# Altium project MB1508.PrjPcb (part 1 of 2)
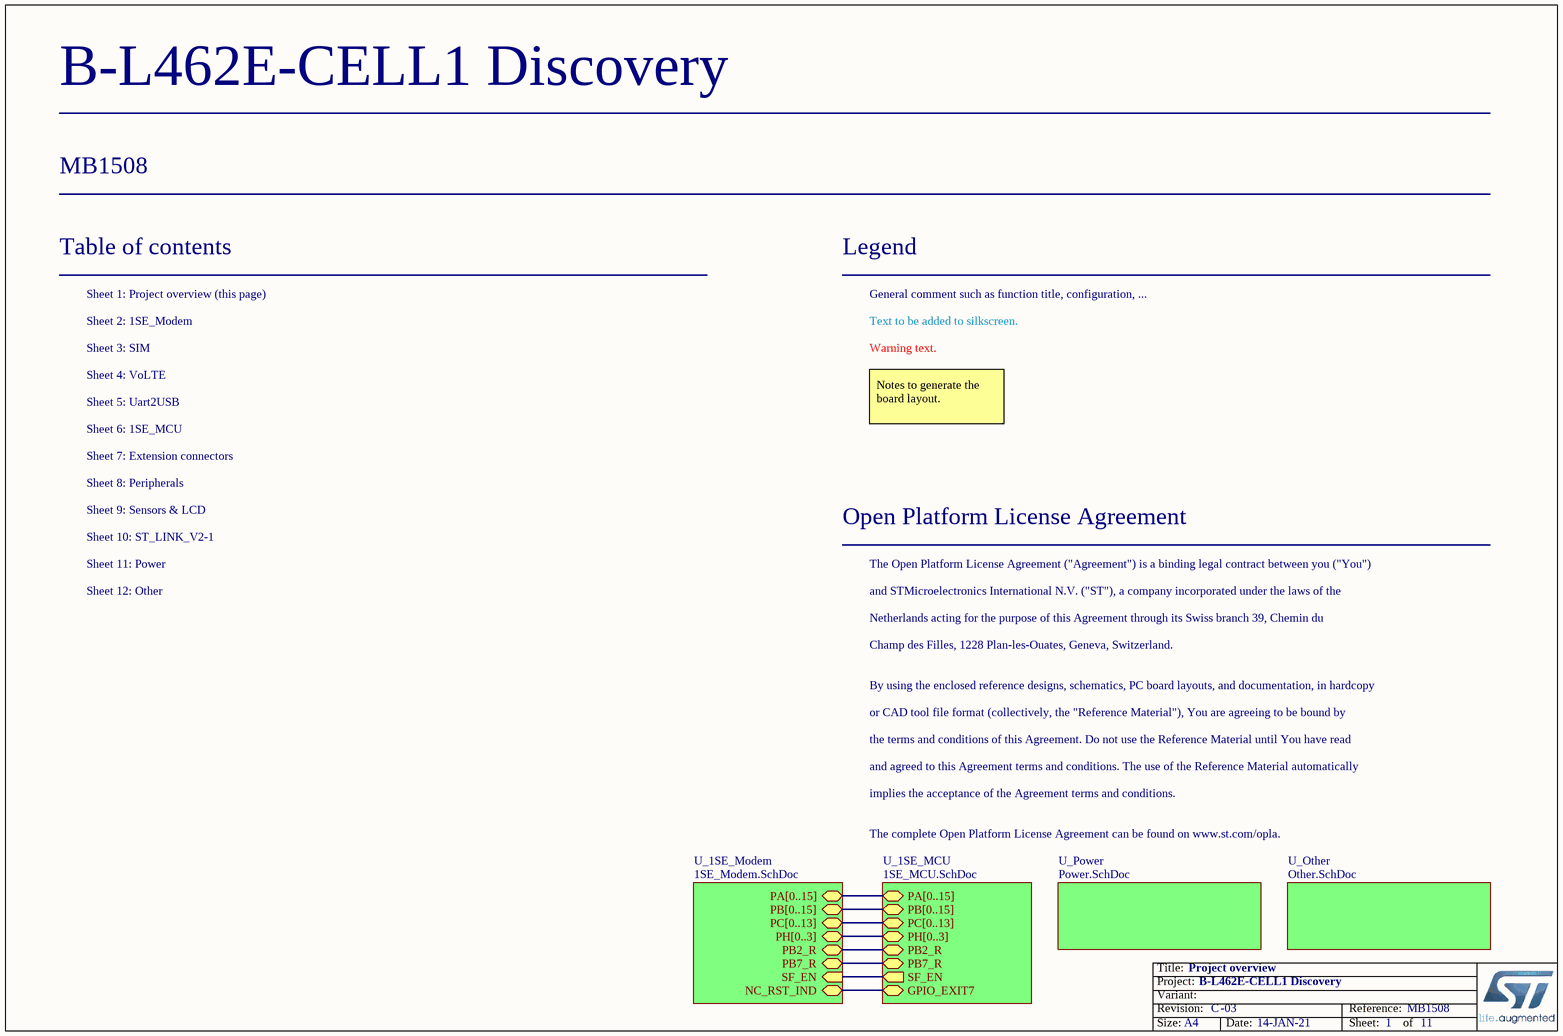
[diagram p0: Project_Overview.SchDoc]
Board_Reference: MB1508; Board_PCB_Revision: C; Board_Name: B-L462E-CELL1 Discovery; Board_Document_Date: 14-JAN-21; Board_Assembly_Revision: 03
12 sheets, 408 parts. Net scope: hierarchical (ports join the sheet entries above them; power ports are global).
Board file: MB1508.PcbDoc
Sheets:
  Project_Overview.SchDoc
    U_Power = Power.SchDoc
    U_1SE_Modem = 1SE_Modem.SchDoc
      U_VoLTE = VoLTE.SchDoc
      U_Uart2USB = Uart2USB.SchDoc
      U_SIM = SIM.SchDoc
    U_1SE_MCU = 1SE_MCU.SchDoc
      U_Extension connectors = Extension connectors.SchDoc
      U_Peripherals = Peripherals.SchDoc
      U_Sensors & LCD = Sensors & LCD.SchDoc
      U_ST_LINK_V2-1 = ST_LINK_V2-1.SchDoc
    U_Other = Other.SchDoc

## Sheet Project_Overview.SchDoc: Project overview
size A4; Date: Not used; ApprovedBy: Not used; CheckedBy: Not used; Author: Not used; CompanyName: STMicroelectronics; DrawnBy: Not used; Engineer: Not used; Organization: Not used; Address1: Not used; Address2: Not used; Address3: Not used; Address4: Not used; DocumentNumber: Not used; Revision: Not used; SheetNumber: 1; SheetTotal: 11

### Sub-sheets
U_1SE_MCU = 1SE_MCU.SchDoc: SF_EN (out), GPIO_EXIT7 (bidir), PA[0..15] (bidir), PB[0..15] (bidir), PC[0..13] (bidir), PH[0..3] (bidir), PB7_R (bidir), PB2_R (bidir)
U_1SE_Modem = 1SE_Modem.SchDoc: PA[0..15] (bidir), PB[0..15] (bidir), PC[0..13] (bidir), PH[0..3] (bidir), NC_RST_IND (bidir), PB7_R (bidir), PB2_R (bidir), SF_EN (in)
U_Other = Other.SchDoc: no entries
U_Power = Power.SchDoc: no entries

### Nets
NC_RST_IND: sheet U_1SE_Modem/NC_RST_IND, sheet U_1SE_MCU/GPIO_EXIT7
PB2_R: sheet U_1SE_Modem/PB2_R, sheet U_1SE_MCU/PB2_R
PB7_R: sheet U_1SE_Modem/PB7_R, sheet U_1SE_MCU/PB7_R
SF_EN: sheet U_1SE_Modem/SF_EN, sheet U_1SE_MCU/SF_EN

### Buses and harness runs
bus sheet U_1SE_MCU/PA[0..15] = sheet U_1SE_Modem/PA[0..15]
bus sheet U_1SE_MCU/PB[0..15] = sheet U_1SE_Modem/PB[0..15]
bus sheet U_1SE_MCU/PC[0..13] = sheet U_1SE_Modem/PC[0..13]
bus sheet U_1SE_MCU/PH[0..3] = sheet U_1SE_Modem/PH[0..3]

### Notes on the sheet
- Table of contents
- Sheet 1: Project overview (this page)
- Legend
- General comment such as function title, configuration, ...
- Sheet 2: 1SE_Modem
- Sheet 3: SIM
- Sheet 4: VoLTE
- Text to be added to silkscreen.
- Warning text.
- Sheet 6: 1SE_MCU
- Sheet 5: Uart2USB
- Notes to generate the board layout.
- Sheet 7: Extension connectors
- Sheet 9: Sensors & LCD
- Sheet 8: Peripherals
- Sheet 11: Power
- Sheet 10: ST_LINK_V2-1
- Open Platform License Agreement
- The Open Platform License Agreement ("Agreement") is a binding legal contract between you ("You")
- Sheet 12: Other
- and STMicroelectronics International N.V. ("ST"), a company incorporated under the laws of the
- Netherlands acting for the purpose of this Agreement through its Swiss branch 39, Chemin du
- Champ des Filles, 1228 Plan-les-Ouates, Geneva, Switzerland.
- By using the enclosed reference designs, schematics, PC board layouts, and documentation, in hardcopy
- or CAD tool file format (collectively, the "Reference Material"), You are agreeing to be bound by
- the terms and conditions of this Agreement. Do not use the Reference Material until You have read
- and agreed to this Agreement terms and conditions. The use of the Reference Material automatically
- implies the acceptance of the Agreement terms and conditions.
- The complete Open Platform License Agreement can be found on www.st.com/opla.

## Sheet Power.SchDoc: Power
size A4; Date: Not used; ApprovedBy: Not used; CheckedBy: Not used; Author: Not used; CompanyName: STMicroelectronics; DrawnBy: Not used; Engineer: Not used; Organization: Not used; Address1: Not used; Address2: Not used; Address3: Not used; Address4: Not used; DocumentNumber: Not used; Revision: Not used; SheetNumber: 11; SheetTotal: 12
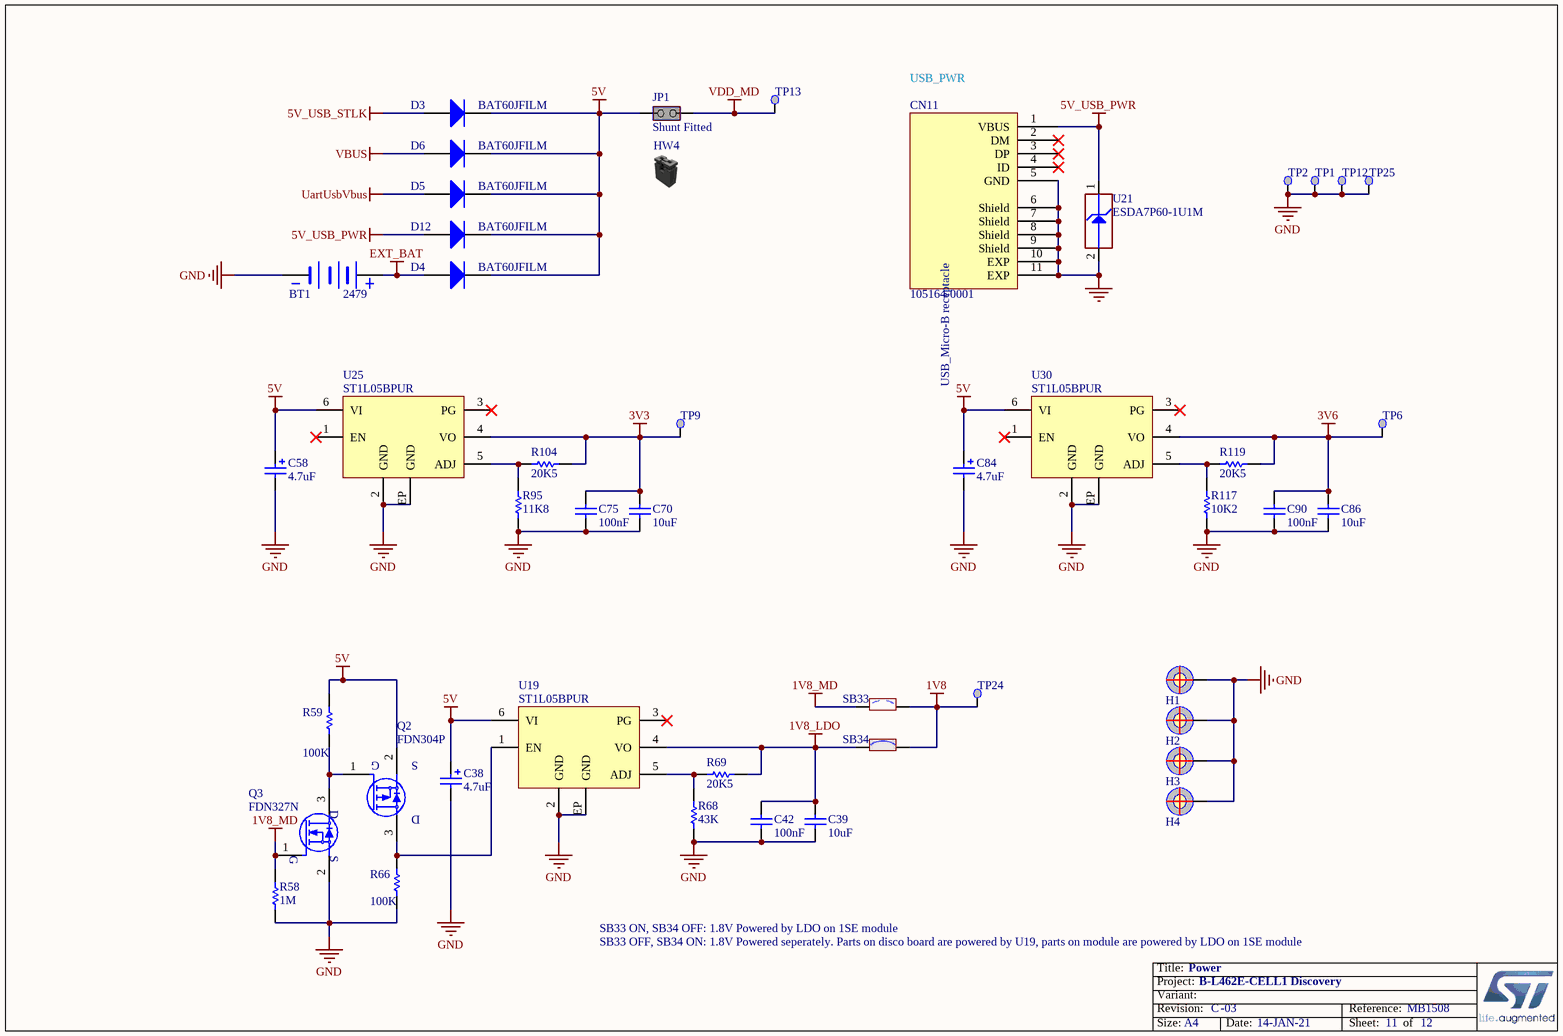
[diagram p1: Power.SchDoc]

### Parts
BT1  value 2479  [BAT_KEYSTONE_PC-MOUNT-2479_HOLDER_AAA_X3]  (hidden comment: BATTERY HOLDER 3 x AAA)
C38  value 4.7uF  [CPOL_TAJ-A_1206_H180]  (hidden comment: Cap_POL_TANA)
C39  value 10uF  [C0805]  (hidden comment: Capacitor)
C42  value 100nF  [C0603]  (hidden comment: Capacitor)
C58  value 4.7uF  [CPOL_TAJ-A_1206_H180]  (hidden comment: Cap_POL_TANA)
C70  value 10uF  [C0805]  (hidden comment: Capacitor)
C75  value 100nF  [C0603]  (hidden comment: Capacitor)
C84  value 4.7uF  [CPOL_TAJ-A_1206_H180]  (hidden comment: Cap_POL_TANA)
C86  value 10uF  [C0805]  (hidden comment: Capacitor)
C90  value 100nF  [C0603]  (hidden comment: Capacitor)
CN11  value 105164-0001  [CON_USBMICROB_MOLEX_105164-0001_H2P45]  (hidden comment: USB_uB_105164-0001)
D3  BAT60JFILM  [DIO_SOD323]
D4  BAT60JFILM  [DIO_SOD323]
D5  BAT60JFILM  [DIO_SOD323]
D6  BAT60JFILM  [DIO_SOD323]
D12  BAT60JFILM  [DIO_SOD323]
H1  POSITION HOLE  [PTH_M1261-3005-N_3P5X6_M3_H14]  (value not drawn)  (no BOM)
H2  POSITION HOLE  [PTH_M1261-3005-N_3P5X6_M3_H14]  (value not drawn)  (no BOM)
H3  POSITION HOLE  [PTH_M1261-3005-N_3P5X6_M3_H14]  (value not drawn)  (no BOM)
H4  POSITION HOLE  [PTH_M1261-3005-N_3P5X6_M3_H14]  (value not drawn)  (no BOM)
HW4  Shunt Black 2.54mm  (value not drawn)  (mechanical)
JP1  value Shunt Fitted  [CON_SAMTEC_TSW-102-07-G-S]  (hidden comment: Jumper_Header 2x1 Fitted)
Q2  value FDN304P  [MOS_SOT23]  (hidden comment: MOSFET_FDN304P)
Q3  value FDN327N  [MOS_SOT23]  (hidden comment: BSN20)
R58  value 1M  [R0603]  (hidden comment: Resistor)
R59  value 100K  [R0603]  (hidden comment: Resistor)
R66  value 100K  [R0603]  (hidden comment: Resistor)
R68  value 43K  [R0603]  (hidden comment: Resistor)
R69  value 20K5  [R0603]  (hidden comment: Resistor)
R95  value 11K8  [R0603]  (hidden comment: Resistor)
R104  value 20K5  [R0603]  (hidden comment: Resistor)
R117  value 10K2  [R0603]  (hidden comment: Resistor)
R119  value 20K5  [R0603]  (hidden comment: Resistor)
SB33  SB_OFF  [SOLDER-BRIDGE_R0603-0R]  (value not drawn)
SB34  SB_ON  [SOLDER-BRIDGE_R0603-0R]  (value not drawn)
TP1  Test Point  [TP_SMD_1MM]  (value not drawn)  (no BOM)
TP2  Test Point  [TP_SMD_1MM]  (value not drawn)  (no BOM)
TP6  Test Point  [TP_SMD_1MM]  (value not drawn)  (no BOM)
TP9  Test Point  [TP_SMD_1MM]  (value not drawn)  (no BOM)
TP12  Test Point  [TP_SMD_1MM]  (value not drawn)  (no BOM)
TP13  Test Point  [TP_SMD_1MM]  (value not drawn)  (no BOM)
TP24  Test Point  [TP_SMD_1MM]  (value not drawn)  (no BOM)
TP25  Test Point  [TP_SMD_1MM]  (value not drawn)  (no BOM)
U19  ST1L05BPUR  [ICC_DFN6-EPAD_3X3_P095]
U21  value ESDA7P60-1U1M  [ESD_QFN2_1P6X1_P125]  (hidden comment: ESD-TRANSIL)
U25  ST1L05BPUR  [ICC_DFN6-EPAD_3X3_P095]
U30  ST1L05BPUR  [ICC_DFN6-EPAD_3X3_P095]

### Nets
1V8: SB33.2 SB34.2 TP24.1
1V8_LDO: C39.1 C42.2 R69.2 SB34.1 U19.4(VO)
1V8_MD: Q3.1(G) R58.2 SB33.1
3V3: C70.1 C75.2 R104.2 TP9.1 U25.4(VO)
3V6: C86.1 C90.2 R119.2 TP6.1 U30.4(VO)
5V: C38.1 C58.1 C84.1 D3.2(K) D4.2(K) D5.2(K) D6.2(K) D12.2(K) JP1.1(COMMON) Q2.2(S) R59.2 U19.6(VI) U25.6(VI) U30.6(VI)
5V_USB_PWR: CN11.1(VBUS) D12.1(A) U21.1(IO1)
5V_USB_STLK: D3.1(A)
EXT_BAT: BT1.1(+) D4.1(A)
GND: BT1.2(-) C38.2 C39.2 C42.1 C58.2 C70.2 C75.1 C84.2 C86.2 C90.1 CN11.5(GND) CN11.6(Shield) CN11.7(Shield) CN11.8(Shield) CN11.9(Shield) CN11.10(EXP) CN11.11(EXP) H1.1 H2.1 H3.1 H4.1 Q3.2(S) R58.1 R66.1 R68.1 R95.1 R117.1 TP1.1 TP2.1 TP12.1 TP25.1 U19.2(GND) U19.EP(GND) U21.2(GND) U25.2(GND) U25.EP(GND) U30.2(GND) U30.EP(GND)
UartUsbVbus: D5.1(A)
VBUS: D6.1(A)
VDD_MD: JP1.2(NO) TP13.1
NetQ2_1: Q2.1(G) Q3.3(D) R59.1
NetQ2_3: Q2.3(D) R66.2 U19.1(EN)
NetR68_2: R68.2 R69.1 U19.5(ADJ)
NetR95_2: R95.2 R104.1 U25.5(ADJ)
NetR117_2: R117.2 R119.1 U30.5(ADJ)

Not connected (* = marked no-connect by the designer): CN11 2(DM)* 3(DP)* 4(ID)*; U19 3(PG)*; U25 1(EN)* 3(PG)*; U30 1(EN)* 3(PG)*

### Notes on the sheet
- USB_PWR
- SB33 ON, SB34 OFF: 1.8V Powered by LDO on 1SE module
- SB33 OFF, SB34 ON: 1.8V Powered seperately. Parts on disco board are powered by U19, parts on module are powered by LDO on 1SE module

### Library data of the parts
BT1 = MCD-01623: 3xAAA ECONOMICAL PLASTIC BATTERY HOLDER; Part_Type: Connector; Part_Preference: Recommended; Manufacturer: KEYSTONE ELECTRONICS
C38 C58 C84 = MCD-00007: Capacitor, Tantalum, 4.7uF, 16V, 4ohms, +/-10%, pkg Type_A (3216 metric), T=1.6mm; Part_Preference: Recommended; Manufacturer: AVX; Manufacturer_Part_Number: TAJA475K016R; Order_Code_RS: 464-9132
C39 C70 C86 = MCD-00014: Capacitor, MLCC, 10uF, 25V, X5R, +/-10%, 0805, T=0,85mm; Part_Preference: Recommended; Manufacturer: YAGEO; Manufacturer_Part_Number: CC0805KRX5R8BB106
C42 C75 C90 = MCD-00237: Capacitor, MLCC, 100nF, 6V3, X5R, +/-10%, 0603, T=0,8mm; Part_Preference: Not recommended; Manufacturer: YAGEO; Manufacturer_Part_Number: CC0603KRX5R5BB104
CN11 = MCD-01698: Micro-USB B Receptacle without Flange, Top Mount, Surface Mount, Lead-Free; Part_Type: Connector; Part_Preference: Recommended; Manufacturer: MOLEX
D3-D6 D12 = MCD-00034: BMS_Part_Number: 9151097; Part_Type: Diode; Part_Preference: Recommended; Manufacturer: STMICROELECTRONICS; Manufacturer_HQ_COO: EU
H1-H4 = MCD-00035: POSITION HOLE C6D3R5; Part_Type: Misc; Part_Preference: Recommended
HW4 = MCD-00043: SHUNT 2.54mm BLACK; Part_Type: Misc; Part_Preference: Recommended; Manufacturer: SAMTEC; Alternate_Manufacturer: JIUBABA; Alternate_Manufacturer_Part_Number: 316102S111A; Value: SNT-100-BK-G
JP1 = MCD-00683: Header, 2x1, 2,54mm, VR, TH, Height 5.84mm/2.54mm - Shunt Fitted by default; Part_Type: Connector; Part_Preference: Recommended; Manufacturer: SAMTEC; Manufacturer_Part_Number: TSW-102-07-G-S; Alternate_Manufacturer: LIANYI; Alternate_Manufacturer_Part_Number: 313102S111116
Q2 = MCD-01494: MOSFET, P-Channel , Vds: -20V, Id: -2.4A, Vgs(th): -1.5V, Vgs(max): +/-8V, Rdson:100mohm@Vgs=-1.8V; Part_Type: IC; Part_Preference: Recommended; Manufacturer: ON SEMICONDUCTOR; Alternate_Manufacturer_Part_Number: FDN304PZ
Q3 = MCD-01163: MOSFET, N-Channel , Vds: 20V, Id: 2A, Vgs(th): 1.5V, Vgs(max): +/-8V, Rdson:120mohm@Vgs=1.8V, Qg=6.3nC; Part_Type: IC; Part_Preference: Recommended; Manufacturer: FAIRCHILD
R58 = MCD-00257: Resistor,1M,0603,1%,1/10W; Part_Preference: Recommended; Manufacturer: YAGEO; Manufacturer_Part_Number: RC0603FR-071ML
R59 R66 = MCD-00223: Resistor,100K,0603,1%,1/10W; Part_Preference: Recommended; Manufacturer: YAGEO; Manufacturer_Part_Number: RC0603FR-07100KL
R68 = MCD-00478: Resistor,43K,0603,1%,1/10W; Part_Preference: Recommended; Manufacturer: YAGEO; Manufacturer_Part_Number: RC0603FR-0743KL
R69 R104 R119 = MCD-01149: Resistor,20K5,0603,1%,1/10W; Part_Preference: Recommended; Manufacturer: YAGEO; Manufacturer_Part_Number: RC0603FR-0720K5L
R95 = MCD-00244: Resistor,11K8,0603,1%,1/10W; Part_Preference: Recommended; Manufacturer: YAGEO; Manufacturer_Part_Number: RC0603FR-0711K8L
R117 = MCD-01155: Resistor,10K2,0603,1%,1/10W; Part_Preference: Recommended; Manufacturer: YAGEO; Manufacturer_Part_Number: RC0603FR-0710K2L
SB33 = MCD-00072: Solder Bridge OFF; Part_Type: Misc; Part_Preference: Recommended; Manufacturer: YAGEO; Manufacturer_Part_Number: RC0603JR-070RL
SB34 = MCD-00071: Solder Bridge ON; Part_Type: Misc; Part_Preference: Recommended; Manufacturer: YAGEO; Manufacturer_Part_Number: RC0603JR-070RL
TP1 TP2 TP6 TP9 TP12 TP13 TP24 TP25 = MCD-00074: Test Point 1mm; Part_Type: Misc; Part_Preference: Recommended
U19 U25 U30 = MCD-00581: LDO Linear Voltage Regulator IC Positive Adjustable 1 Output Adjustable 1.3A 6-DFN (3x3); BMS_Part_Number: 9176239; Part_Preference: Recommended; Manufacturer: STMICROELECTRONICS; Manufacturer_HQ_COO: EU
U21 = MCD-00251: High power transient voltage suppressor, 7V breakdown; BMS_Part_Number: 9179042; Part_Type: Diode; Part_Preference: Recommended; Manufacturer: STMICROELECTRONICS; Manufacturer_HQ_COO: EU

## Sheet 1SE_Modem.SchDoc: 1SE_Modem
size A4; Date: Not used; ApprovedBy: Not used; CheckedBy: Not used; Author: Not used; CompanyName: STMicroelectronics; DrawnBy: Not used; Engineer: Not used; Organization: Not used; Address1: Not used; Address2: Not used; Address3: Not used; Address4: Not used; DocumentNumber: Not used; Revision: Not used; SheetNumber: 2; SheetTotal: 11
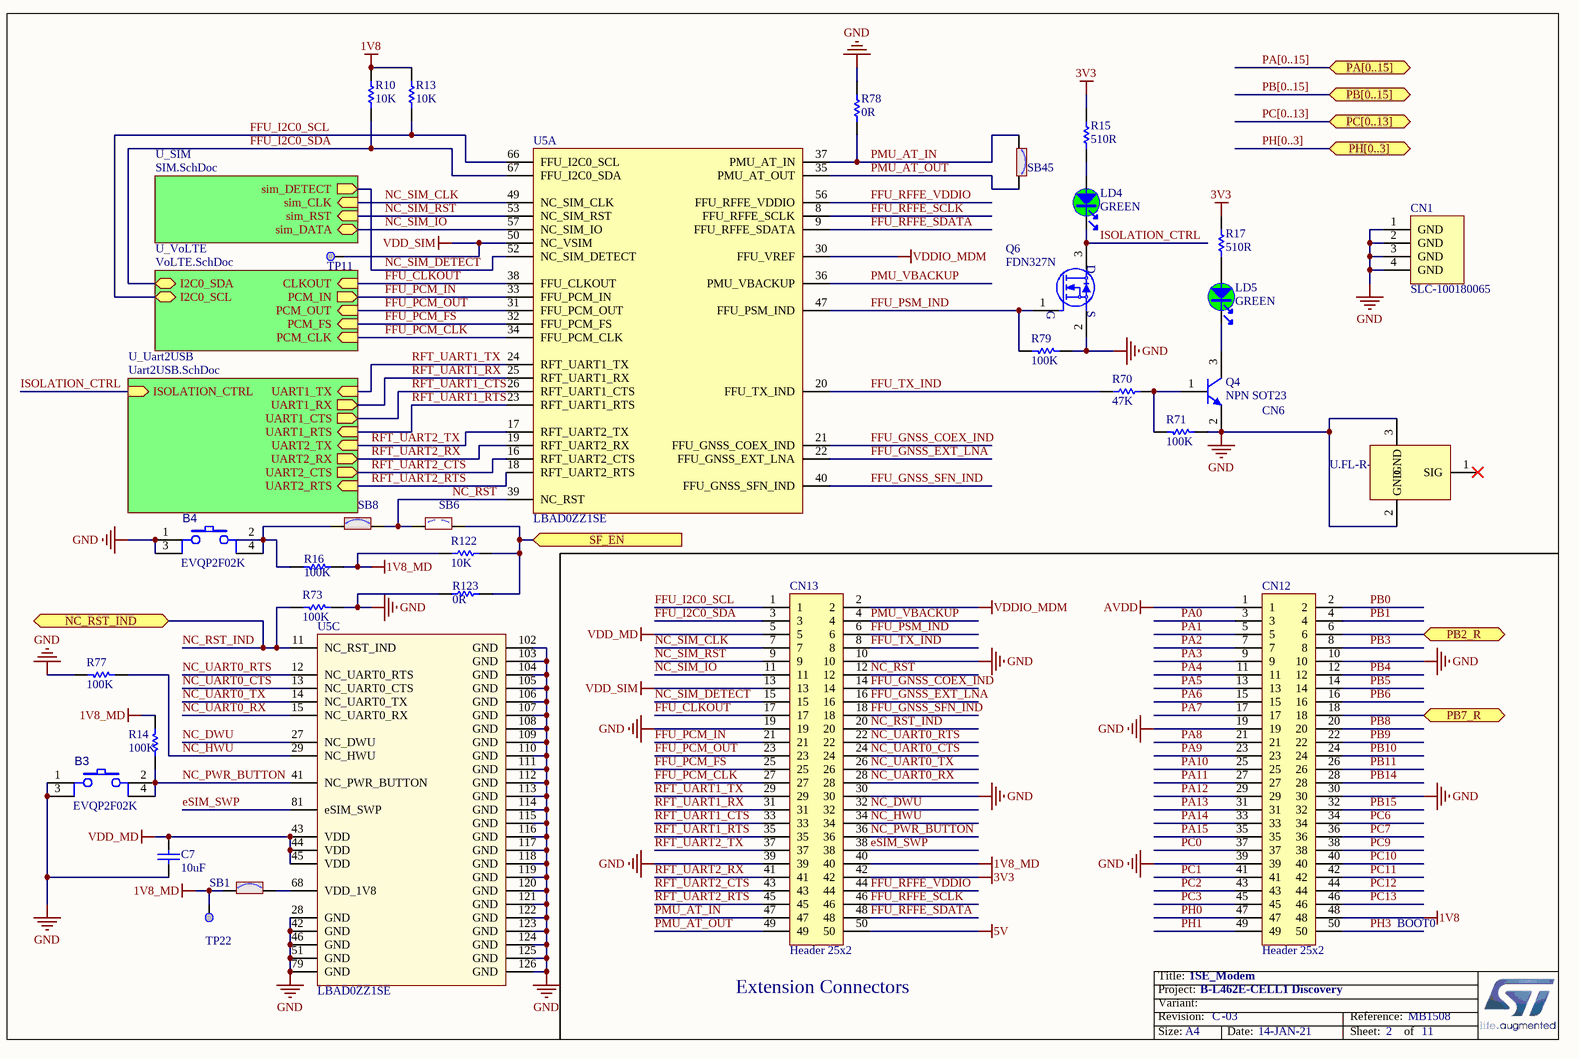
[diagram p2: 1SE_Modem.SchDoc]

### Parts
B3  value EVQP2F02K  [SWI_PANASONIC_EVQP2F02K]  (hidden comment: SW-PUSH-CMS_EVQP2_BLACK)
B4  value EVQP2F02K  [SWI_PANASONIC_EVQP2F02K]  (hidden comment: SW-PUSH-CMS_EVQP2_BLACK)
C7  value 10uF  [C0603]  (hidden comment: Capacitor)
CN1  SLC-100180065  [CON_ROHO_SMA_RFSMARA-7053]
CN6  U.FL-R-SMT-1  [CON_HRS_U.FL-R-SMT-1]
CN12  Header 25x2  [CON_SAMTEC_TSM-125-01-F-DV-A]
CN13  Header 25x2  [CON_SAMTEC_TSM-125-01-F-DV-A]
LD4  value GREEN  [LED_0603_GREEN_H0P8]  (hidden comment: LED_green)
LD5  value GREEN  [LED_0603_GREEN_H0P8]  (hidden comment: LED_green)
Q4  value NPN SOT23  [NPN_SOT23]  (hidden comment: 9013-SOT23)
Q6  value FDN327N  [MOS_SOT23]  (hidden comment: BSN20)
R10  value 10K  [R0603]  (hidden comment: Resistor)
R13  value 10K  [R0603]  (hidden comment: Resistor)
R14  value 100K  [R0603]  (hidden comment: Resistor)
R15  value 510R  [R0603]  (hidden comment: Resistor)
R16  value 100K  [R0603]  (hidden comment: Resistor)
R17  value 510R  [R0603]  (hidden comment: Resistor)
R70  value 47K  [R0603]  (hidden comment: Resistor)
R71  value 100K  [R0603]  (hidden comment: Resistor)
R73  value 100K  [R0603]  (hidden comment: Resistor)
R77  value 100K  [R0603]  (hidden comment: Resistor)
R78  value 0R  [R0603]  (hidden comment: Resistor)
R79  value 100K  [R0603]  (hidden comment: Resistor)
R122  value 10K  [R0603]  (hidden comment: Resistor)
R123  value 0R  [R0603]  (hidden comment: Resistor)
SB1  SB_ON  [SOLDER-BRIDGE_R0603-0R]  (value not drawn)
SB6  SB_OFF  [SOLDER-BRIDGE_R0603-0R]  (value not drawn)
SB8  SB_ON  [SOLDER-BRIDGE_R0603-0R]  (value not drawn)
SB45  SB_ON  [SOLDER-BRIDGE_R0603-0R]  (value not drawn)
TP11  Test Point  [TP_SMD_1MM]  (value not drawn)  (no BOM)
TP22  Test Point  [TP_SMD_1MM]  (value not drawn)  (no BOM)
U5  value LBAD0ZZ1SE  [MOD_BOARD_MURATA_TYPE-1SE_ES3]  (hidden comment: NBIoT_Mod_Type1SE)  (parts A,C of 3)

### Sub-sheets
U_SIM = SIM.SchDoc: sim_CLK (in), sim_DATA (bidir), sim_RST (in), sim_DETECT (out)
U_Uart2USB = Uart2USB.SchDoc: UART1_TX (in), UART1_RX (out), UART1_CTS (out), UART1_RTS (in), UART2_RX (out), UART2_CTS (out), UART2_TX (in), UART2_RTS (in), ISOLATION_CTRL (in)
U_VoLTE = VoLTE.SchDoc: CLKOUT (in), PCM_IN (out), PCM_OUT (in), PCM_FS (in), PCM_CLK (in), I2C0_SCL (bidir), I2C0_SDA (bidir)

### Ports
NC_RST_IND (bidir), PA[0..15] (bidir), PB2_R (bidir), PB7_R (bidir), PB[0..15] (bidir), PC[0..13] (bidir), PH[0..3] (bidir), SF_EN (in)

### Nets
1V8: CN12.48 R10.2 R13.2
1V8_MD: CN13.40 R14.1 R16.2 R122.2 SB1.1 TP22.1
3V3: CN13.42 R15.2 R17.2
5V: CN13.50
AVDD: CN12.1
GND: B3.1 B3.3 B4.1 B4.3 C7.1 CN1.1(GND) CN1.2(GND) CN1.3(GND) CN1.4(GND) CN6.2(GND) CN6.3(GND) CN12.10 CN12.19 CN12.30 CN12.39 CN13.10 CN13.19 CN13.30 CN13.39 Q4.2(E) Q6.2(S) R71.1 R73.2 R77.1 R78.2 R79.1 R123.2 U5.28(GND) U5.42(GND) U5.46(GND) U5.51(GND) U5.79(GND) U5.102(GND) U5.103(GND) U5.104(GND) U5.105(GND) U5.106(GND) U5.107(GND) U5.108(GND) U5.109(GND) U5.110(GND) U5.111(GND) U5.112(GND) U5.113(GND) U5.114(GND) U5.115(GND) U5.116(GND) U5.117(GND) U5.118(GND) U5.119(GND) U5.120(GND) U5.121(GND) U5.122(GND) U5.123(GND) U5.124(GND) U5.125(GND) U5.126(GND)
VDD_MD: C7.2 CN13.5 U5.43(VDD) U5.44(VDD) U5.45(VDD)
VDD_SIM: CN13.13 TP11.1 U5.50(NC_VSIM)
VDDIO_MDM: CN13.2 U5.30(FFU_VREF)
eSIM_SWP: CN13.38 U5.81(eSIM_SWP)
FFU_CLKOUT: CN13.17 U5.38(FFU_CLKOUT) ; sheet U_VoLTE/CLKOUT
FFU_GNSS_COEX_IND: CN13.14 U5.21(FFU_GNSS_COEX_IND)
FFU_GNSS_EXT_LNA: CN13.16 U5.22(FFU_GNSS_EXT_LNA)
FFU_GNSS_SFN_IND: CN13.18 U5.40(FFU_GNSS_SFN_IND)
FFU_I2C0_SCL: CN13.1 R13.1 U5.66(FFU_I2C0_SCL) ; sheet U_VoLTE/I2C0_SCL
FFU_I2C0_SDA: CN13.3 R10.1 U5.67(FFU_I2C0_SDA) ; sheet U_VoLTE/I2C0_SDA
FFU_PCM_CLK: CN13.27 U5.34(FFU_PCM_CLK) ; sheet U_VoLTE/PCM_CLK
FFU_PCM_FS: CN13.25 U5.32(FFU_PCM_FS) ; sheet U_VoLTE/PCM_FS
FFU_PCM_IN: CN13.21 U5.33(FFU_PCM_IN) ; sheet U_VoLTE/PCM_IN
FFU_PCM_OUT: CN13.23 U5.31(FFU_PCM_OUT) ; sheet U_VoLTE/PCM_OUT
FFU_PSM_IND: CN13.6 Q6.1(G) R79.2 U5.47(FFU_PSM_IND)
FFU_RFFE_SCLK: CN13.46 U5.8(FFU_RFFE_SCLK)
FFU_RFFE_SDATA: CN13.48 U5.9(FFU_RFFE_SDATA)
FFU_RFFE_VDDIO: CN13.44 U5.56(FFU_RFFE_VDDIO)
FFU_TX_IND: CN13.8 R70.2 U5.20(FFU_TX_IND)
ISOLATION_CTRL: LD4.2 Q6.3(D) ; sheet U_Uart2USB/ISOLATION_CTRL
NC_DWU: CN13.32 U5.27(NC_DWU)
NC_HWU: CN13.34 R77.2 U5.29(NC_HWU)
NC_PWR_BUTTON: B3.2 B3.4 CN13.36 R14.2 U5.41(NC_PWR_BUTTON)
NC_RST: CN13.12 SB6.1 SB8.2 U5.39(NC_RST)
NC_RST_IND: CN13.20 R73.1 U5.11(NC_RST_IND) ; port NC_RST_IND
NC_SIM_CLK: CN13.7 U5.49(NC_SIM_CLK) ; sheet U_SIM/sim_CLK
NC_SIM_DETECT: CN13.15 U5.52(NC_SIM_DETECT) ; sheet U_SIM/sim_DETECT
NC_SIM_IO: CN13.11 U5.57(NC_SIM_IO) ; sheet U_SIM/sim_DATA
NC_SIM_RST: CN13.9 U5.53(NC_SIM_RST) ; sheet U_SIM/sim_RST
NC_UART0_CTS: CN13.24 U5.13(NC_UART0_CTS)
NC_UART0_RTS: CN13.22 U5.12(NC_UART0_RTS)
NC_UART0_RX: CN13.28 U5.15(NC_UART0_RX)
NC_UART0_TX: CN13.26 U5.14(NC_UART0_TX)
PA0: CN12.3
PA1: CN12.5
PA2: CN12.7
PA3: CN12.9
PA4: CN12.11
PA5: CN12.13
PA6: CN12.15
PA7: CN12.17
PA8: CN12.21
PA9: CN12.23
PA10: CN12.25
PA11: CN12.27
PA12: CN12.29
PA13: CN12.31
PA14: CN12.33
PA15: CN12.35
PB0: CN12.2
PB1: CN12.4
PB2_R: CN12.6 ; port PB2_R
PB3: CN12.8
PB4: CN12.12
PB5: CN12.14
PB6: CN12.16
PB7_R: CN12.18 ; port PB7_R
PB8: CN12.20  [project net I2C1_SCL]
PB9: CN12.22  [project net I2C1_SDA]
PB10: CN12.24
PB11: CN12.26
PB14: CN12.28
PB15: CN12.32
PC0: CN12.37
PC1: CN12.41
PC2: CN12.43
PC3: CN12.45
PC6: CN12.34
PC7: CN12.36
PC9: CN12.38
PC10: CN12.40
PC11: CN12.42
PC12: CN12.44
PC13: CN12.46
PH0: CN12.47  [project net MCO]
PH1: CN12.49
PH3: CN12.50
PMU_AT_IN: CN13.47 R78.1 SB45.1 U5.37(PMU_AT_IN)
PMU_AT_OUT: CN13.49 SB45.2 U5.35(PMU_AT_OUT)
PMU_VBACKUP: CN13.4 U5.36(PMU_VBACKUP)
RFT_UART1_CTS: CN13.33 U5.26(RFT_UART1_CTS) ; sheet U_Uart2USB/UART1_CTS
RFT_UART1_RTS: CN13.35 U5.23(RFT_UART1_RTS) ; sheet U_Uart2USB/UART1_RTS
RFT_UART1_RX: CN13.31 U5.25(RFT_UART1_RX) ; sheet U_Uart2USB/UART1_RX
RFT_UART1_TX: CN13.29 U5.24(RFT_UART1_TX) ; sheet U_Uart2USB/UART1_TX
RFT_UART2_CTS: CN13.43 U5.16(RFT_UART2_CTS) ; sheet U_Uart2USB/UART2_CTS
RFT_UART2_RTS: CN13.45 U5.18(RFT_UART2_RTS) ; sheet U_Uart2USB/UART2_RTS
RFT_UART2_RX: CN13.41 U5.19(RFT_UART2_RX) ; sheet U_Uart2USB/UART2_RX
RFT_UART2_TX: CN13.37 U5.17(RFT_UART2_TX) ; sheet U_Uart2USB/UART2_TX
SF_EN: R122.1 R123.1 SB6.2 ; port SF_EN
NetB4_2: B4.2 B4.4 R16.1 SB8.1
NetLD4_1: LD4.1 R15.1
NetLD5_1: LD5.1 R17.1
NetLD5_2: LD5.2 Q4.3(C)
NetQ4_1: Q4.1(B) R70.1 R71.2
NetSB1_2: SB1.2 U5.68(VDD_1V8)

Not connected (* = marked no-connect by the designer): CN6 1(SIG)*

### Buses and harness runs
bus PA[0..15] = port PA[0..15]
bus PB[0..15] = port PB[0..15]
bus PC[0..13] = port PC[0..13]
bus PH[0..3] = port PH[0..3]

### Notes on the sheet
- BOOT0
- (near CN13) Extension Connectors

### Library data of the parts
B3 B4 = MCD-00168: EVQP2 - 4.7mm x 3.5 mm SMD Light Touch Switch; Part_Type: Misc; Part_Preference: Recommended; Manufacturer: PANASONIC
C7 = MCD-01341: Capacitor, MLCC, 10uF, 6V3, X5R, +/-20%, 0603, T=0,8mm; Part_Preference: Recommended; Manufacturer: MURATA; Manufacturer_Part_Number: GRM188R60J106ME47D; Alternate_Manufacturer_Part_Number: GRM188R60J106ME84D
CN1 = MCD-01701: RF Coxial Cable to uFL; Part_Type: Misc; Part_Preference: Recommended; Manufacturer: SENLING
CN6 = MCD-01583: U.FL RF connector; BMS_Part_Number: 9187005; Part_Preference: Recommended; Manufacturer: HIROSE; Alternate_Manufacturer: SUNLIGHT; Alternate_Manufacturer_Part_Number: SL2-240006-A; Order_Code_RS: 557-981
CN12 CN13 = MCD-01931: Header, 25x2, 2,54mm, VR, TH, Height 5.84mm/2.54mm, with alignment Pin; Part_Type: Connector; Part_Preference: Recommended; Manufacturer: SAMTEC; Manufacturer_Part_Number: TSM-125-01-F-DV-A; Alternate_Manufacturer: CNT; Alternate_Manufacturer_Part_Number: CNT-M254-2*25-GM-6/3.2/7-P
LD4 LD5 = MCD-00320: LED, Green, 0603; Part_Type: Display; Part_Preference: Not recommended; Manufacturer: EVERLIGHT; Manufacturer_Part_Number: 19-213SYGC/S530-E2/TR8
Q4 = MCD-00073: NPN Bipolar Transistor; Part_Type: IC; Part_Preference: Recommended; Manufacturer: ON SEMICONDUCTOR; Manufacturer_Part_Number: BSR14; Alternate_Manufacturer_Part_Number: MMBT2222LT1G / MMBT2222ALT1G / MMBT2222ALT3G
Q6 = MCD-01163: as Q3 on sheet Power
R10 R13 R122 = MCD-00220: Resistor,10K,0603,1%,1/10W; Part_Preference: Recommended; Manufacturer: YAGEO; Manufacturer_Part_Number: RC0603FR-0710KL
R14 R16 R71 R73 R77 R79 = MCD-00223: as R59 on sheet Power
R15 R17 = MCD-00225: Resistor,510R,0603,1%,1/10W; Part_Preference: Recommended; Manufacturer: YAGEO; Manufacturer_Part_Number: RC0603FR-07510RL
R70 = MCD-00222: Resistor,47K,0603,1%,1/10W; Part_Preference: Recommended; Manufacturer: YAGEO; Manufacturer_Part_Number: RC0603FR-0747KL
R78 R123 = MCD-00056: Resistor,0R,0603,5%,1/10W; Part_Preference: Recommended; Manufacturer: YAGEO; Manufacturer_Part_Number: RC0603JR-070RL
SB1 SB8 SB45 = MCD-00071: as SB34 on sheet Power
SB6 = MCD-00072: as SB33 on sheet Power
TP11 TP22 = MCD-00074: as TP1 on sheet Power
U5 = MCD-01700: NBIoT Module; BMS_Part_Number: 9154004; Part_Type: IC; Part_Preference: Recommended; Manufacturer: MURATA

## Sheet VoLTE.SchDoc: VoLTE
size A4; Date: Not used; ApprovedBy: Not used; CheckedBy: Not used; Author: Not used; CompanyName: STMicroelectronics; DrawnBy: Not used; Engineer: Not used; Organization: Not used; Address1: Not used; Address2: Not used; Address3: Not used; Address4: Not used; DocumentNumber: Not used; Revision: Not used; SheetNumber: 4; SheetTotal: 11
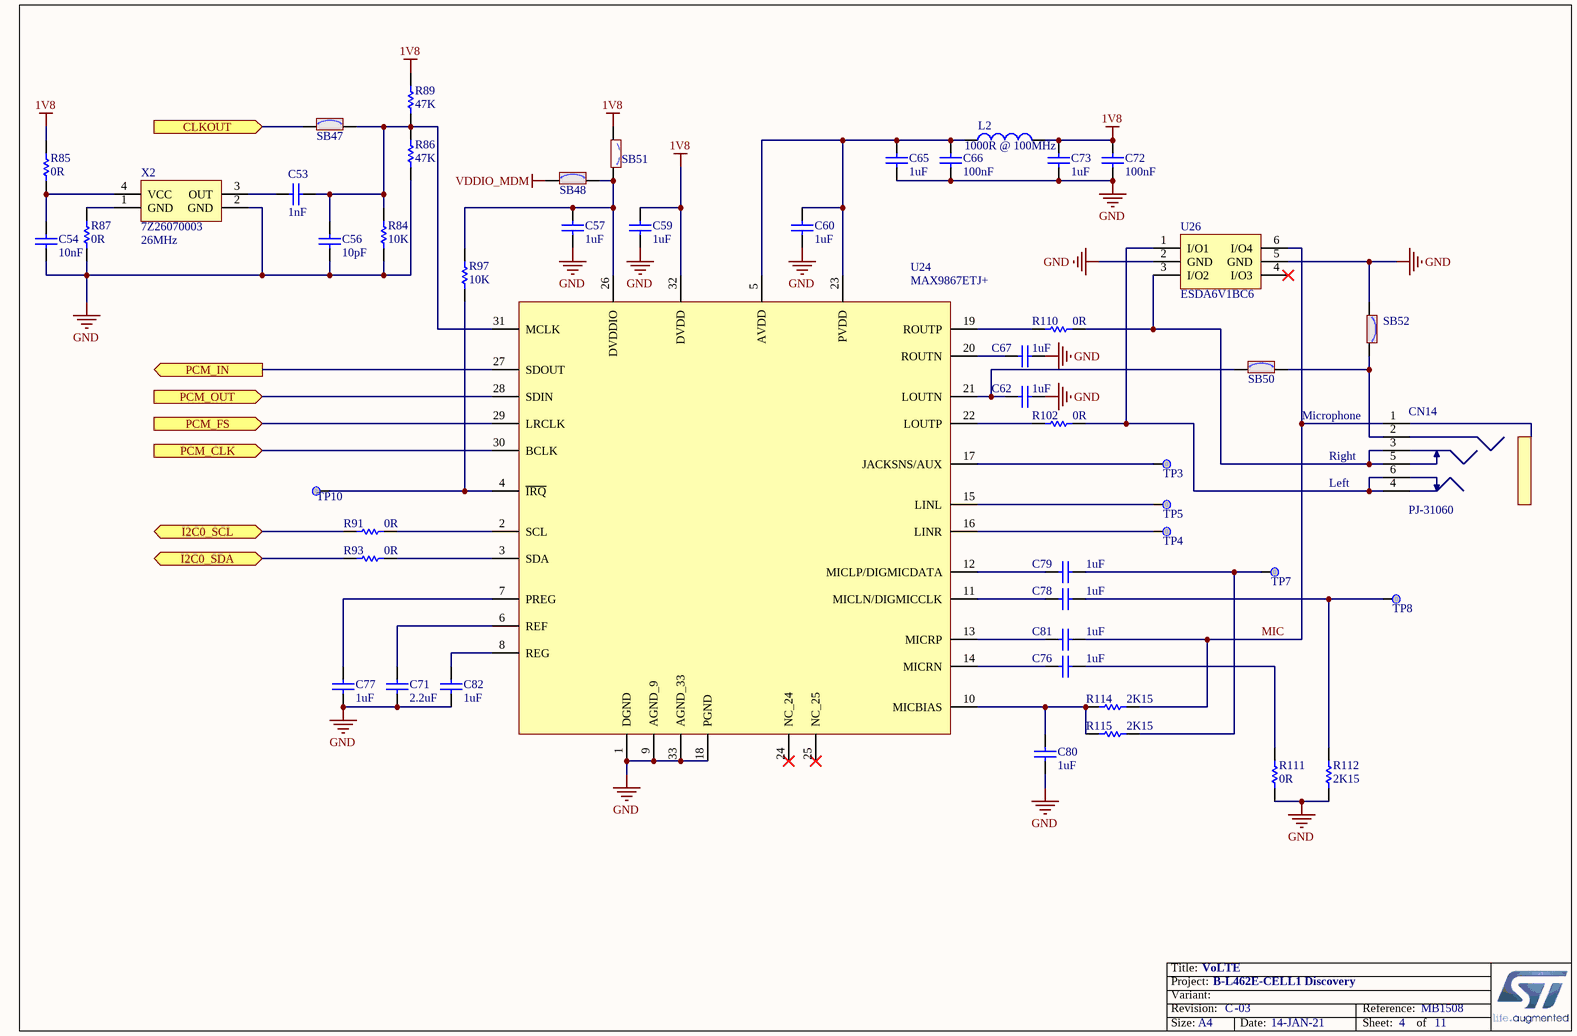
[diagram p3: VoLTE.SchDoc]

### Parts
C53  value 1nF  [C0603]  (hidden comment: Capacitor)
C54  value 10nF  [C0603]  (hidden comment: Capacitor)
C56  value 10pF  [C0603]  (hidden comment: Capacitor)
C57  value 1uF  [C0603]  (hidden comment: Capacitor)
C59  value 1uF  [C0603]  (hidden comment: Capacitor)
C60  value 1uF  [C0603]  (hidden comment: Capacitor)
C62  value 1uF  [C0603]  (hidden comment: Capacitor)
C65  value 1uF  [C0603]  (hidden comment: Capacitor)
C66  value 100nF  [C0603]  (hidden comment: Capacitor)
C67  value 1uF  [C0603]  (hidden comment: Capacitor)
C71  value 2.2uF  [C0603]  (hidden comment: Capacitor)
C72  value 100nF  [C0603]  (hidden comment: Capacitor)
C73  value 1uF  [C0603]  (hidden comment: Capacitor)
C76  value 1uF  [C0603]  (hidden comment: Capacitor)
C77  value 1uF  [C0603]  (hidden comment: Capacitor)
C78  value 1uF  [C0603]  (hidden comment: Capacitor)
C79  value 1uF  [C0603]  (hidden comment: Capacitor)
C80  value 1uF  [C0603]  (hidden comment: Capacitor)
C81  value 1uF  [C0603]  (hidden comment: Capacitor)
C82  value 1uF  [C0603]  (hidden comment: Capacitor)
CN14  PJ-31060  [CON_PHONE-JACK-3P5_TAIYI_PJ31060]
L2  value 1000R @ 100MHz  [L0603_H0P8]  (hidden comment: BEAD)
R84  value 10K  [R0603]  (hidden comment: Resistor)
R85  value 0R  [R0603]  (hidden comment: Resistor)
R86  value 47K  [R0603]  (hidden comment: Resistor)
R87  value 0R  [R0603]  (hidden comment: Resistor)
R89  value 47K  [R0603]  (hidden comment: Resistor)
R91  value 0R  [R0603]  (hidden comment: Resistor)
R93  value 0R  [R0603]  (hidden comment: Resistor)
R97  value 10K  [R0603]  (hidden comment: Resistor)
R102  value 0R  [R0603]  (hidden comment: Resistor)
R110  value 0R  [R0603]  (hidden comment: Resistor)
R111  value 0R  [R0603]  (hidden comment: Resistor)
R112  value 2K15  [R0603]  (hidden comment: Resistor)
R114  value 2K15  [R0603]  (hidden comment: Resistor)
R115  value 2K15  [R0603]  (hidden comment: Resistor)
SB47  SB_ON  [SOLDER-BRIDGE_R0603-0R]  (value not drawn)
SB48  SB_ON  [SOLDER-BRIDGE_R0603-0R]  (value not drawn)
SB50  SB_ON  [SOLDER-BRIDGE_R0603-0R]  (value not drawn)
SB51  SB_OFF  [SOLDER-BRIDGE_R0603-0R]  (value not drawn)
SB52  SB_ON  [SOLDER-BRIDGE_R0603-0R]  (value not drawn)
TP3  Test Point  [TP_SMD_1MM]  (value not drawn)  (no BOM)
TP4  Test Point  [TP_SMD_1MM]  (value not drawn)  (no BOM)
TP5  Test Point  [TP_SMD_1MM]  (value not drawn)  (no BOM)
TP7  Test Point  [TP_SMD_1MM]  (value not drawn)  (no BOM)
TP8  Test Point  [TP_SMD_1MM]  (value not drawn)  (no BOM)
TP10  Test Point  [TP_SMD_1MM]  (value not drawn)  (no BOM)
U24  MAX9867ETJ+  [ICC_TQFN32-EPAD_5X5_H0P75_P050]
U26  ESDA6V1BC6  [ESD_SOT23-6L]
X2  7Z26070003  value 26MHz  [CRY_NDK_NT2016SB_4P]

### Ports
CLKOUT (in), I2C0_SCL (bidir), I2C0_SDA (bidir), PCM_CLK (in), PCM_FS (in), PCM_IN (out), PCM_OUT (in)

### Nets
1V8: C59.1 C72.2 C73.1 L2.2 R85.2 R89.2 SB51.1 U24.32(DVDD)
GND: C54.1 C56.1 C57.2 C59.2 C60.2 C62.2 C65.2 C66.1 C67.2 C71.1 C72.1 C73.2 C77.1 C80.1 C82.1 R84.2 R86.1 R87.1 R111.1 R112.1 SB52.1 U24.1(DGND) U24.9(AGND_9) U24.18(PGND) U24.33(AGND_33) U26.2(GND) U26.5(GND) X2.2(GND)
VDDIO_MDM: SB48.1
FFU_CLKOUT: SB47.1 ; port CLKOUT
FFU_I2C0_SCL: R91.1 ; port I2C0_SCL
FFU_I2C0_SDA: R93.1 ; port I2C0_SDA
FFU_PCM_CLK: U24.30(BCLK) ; port PCM_CLK
FFU_PCM_FS: U24.29(LRCLK) ; port PCM_FS
FFU_PCM_IN: U24.27(SDOUT) ; port PCM_IN
FFU_PCM_OUT: U24.28(SDIN) ; port PCM_OUT
MIC: C81.1 CN14.1 R114.1 U26.6(I/O4)
NetC53_1: C53.1 X2.3(OUT)
NetC53_2: C53.2 C56.2 R84.1 R86.2 R89.1 SB47.2 U24.31(MCLK)
NetC54_2: C54.2 R85.1 X2.4(VCC)
NetC57_1: C57.1 R97.1 SB48.2 SB51.2 U24.26(DVDDIO)
NetC60_1: C60.1 C65.1 C66.2 L2.1 U24.5(AVDD) U24.23(PVDD)
NetC62_1: C62.1 SB50.1 U24.21(LOUTN)
NetC67_1: C67.1 U24.20(ROUTN)
NetC71_2: C71.2 U24.6(REF)
NetC76_1: C76.1 R111.2
NetC76_2: C76.2 U24.14(MICRN)
NetC77_2: C77.2 U24.7(PREG)
NetC78_1: C78.1 R112.2 TP8.1
NetC78_2: C78.2 U24.11(MICLN/DIGMICCLK)
NetC79_1: C79.1 R115.1 TP7.1
NetC79_2: C79.2 U24.12(MICLP/DIGMICDATA)
NetC80_2: C80.2 R114.2 R115.2 U24.10(MICBIAS)
NetC81_2: C81.2 U24.13(MICRP)
NetC82_2: C82.2 U24.8(REG)
NetCN14_2: CN14.2 SB50.2 SB52.2
NetCN14_3: CN14.3 CN14.5 R110.2 U26.3(I/O2)
NetCN14_4: CN14.4 CN14.6 R102.2 U26.1(I/O1)
NetR87_2: R87.2 X2.1(GND)
NetR91_2: R91.2 U24.2(SCL)
NetR93_2: R93.2 U24.3(SDA)
NetR97_2: R97.2 TP10.1 U24.4(~{IRQ})
NetR102_1: R102.1 U24.22(LOUTP)
NetR110_1: R110.1 U24.19(ROUTP)
NetTP3_1: TP3.1 U24.17(JACKSNS/AUX)
NetTP4_1: TP4.1 U24.16(LINR)
NetTP5_1: TP5.1 U24.15(LINL)

Not connected (* = marked no-connect by the designer): U24 24(NC_24)* 25(NC_25)*; U26 4(I/O3)*

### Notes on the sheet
- Microphone
- Left
- (near CN14) Right

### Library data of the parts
C53 = MCD-00273: Capacitor, MLCC, 1nF, 16V, X7R, +/-10%, 0603, T=0,8mm; Part_Preference: Recommended; Manufacturer: YAGEO; Manufacturer_Part_Number: CC0603KRX7R7BB102
C54 = MCD-01007: Capacitor, MLCC, 10nF, 16V, X7R, +/-10%, 0603, T=0.8mm; Part_Preference: Recommended; Manufacturer: YAGEO; Manufacturer_Part_Number: CC0603KRX7R7BB103
C56 = MCD-00637: Capacitor, MLCC, 10pF, 50V, NPO, +/-5%, 0603, T=0,8mm; Part_Preference: Recommended; Manufacturer: YAGEO; Manufacturer_Part_Number: CC0603JRNPO9BN100
C57 C59 C60 C62 C65 C67 C73 C76-C82 = MCD-00238: Capacitor, MLCC, 1uF, 6V3, X5R, +/-10%, 0603, T=0,8mm; Part_Preference: Recommended; Manufacturer: YAGEO; Manufacturer_Part_Number: CC0603KRX5R5BB105
C66 C72 = MCD-00237: as C42 on sheet Power
C71 = MCD-00551: Capacitor, MLCC, 2.2uF, 10V, X5R, +/-10%, 0603, T=0,8mm; Part_Preference: Not recommended; Manufacturer: KEMET; Manufacturer_Part_Number: C0603C225K8PACTU; Alternate_Manufacturer: YAGEO; Alternate_Manufacturer_Part_Number: CC0603KRX5R6BB225; Order_Code_RS: 691-1158
CN14 = MCD-01695: Connector Jack socket Stereo 3.5mm, SMT; Part_Preference: Recommended; Manufacturer: TAIYI
L2 = MCD-01724: Ferrite bead, 1000R @ 100MHz,  600mA, 350mOhm, 0603; Part_Type: Inductor; Part_Preference: Recommended; Manufacturer: MURATA; Manufacturer_Part_Number: BLM18HE102SN1D
R84 R97 = MCD-00220: as R10 on sheet 1SE_Modem
R85 R87 R91 R93 R102 R110 R111 = MCD-00056: as R78 on sheet 1SE_Modem
R86 R89 = MCD-00222: as R70 on sheet 1SE_Modem
R112 R114 R115 = MCD-01723: Resistor,2K15,0603,1%,1/10W; Part_Preference: Recommended; Manufacturer: YAGEO; Manufacturer_Part_Number: RC0603FR-072K15L
SB47 SB48 SB50 SB52 = MCD-00071: as SB34 on sheet Power
SB51 = MCD-00072: as SB33 on sheet Power
TP3-TP5 TP7 TP8 TP10 = MCD-00074: as TP1 on sheet Power
U24 = MCD-01621: Ultra-Low Power Stereo Audio Codec; Part_Type: IC; Part_Preference: Recommended; Manufacturer: MAXIM INTEGRATED
U26 = MCD-00247: Quad Bidir ESD protection; BMS_Part_Number: 9179038; Part_Type: Diode; Part_Preference: Recommended; Manufacturer: STMICROELECTRONICS; Manufacturer_HQ_COO: EU
X2 = MCD-01836: Oscillator 26Mhz, +-2ppm, Vcc:1.8V typ (1.7V min), square wave: [0.1Vcc;0.9Vcc]; Part_Type: Crystal oscillator; Part_Preference: Recommended; Manufacturer: TXC

## Sheet Uart2USB.SchDoc: Uart2USB
size A4; Date: Not used; ApprovedBy: Not used; CheckedBy: Not used; Author: Not used; CompanyName: STMicroelectronics; DrawnBy: Not used; Engineer: Not used; Organization: Not used; Address1: Not used; Address2: Not used; Address3: Not used; Address4: Not used; DocumentNumber: Not used; Revision: Not used; SheetNumber: 5; SheetTotal: 11
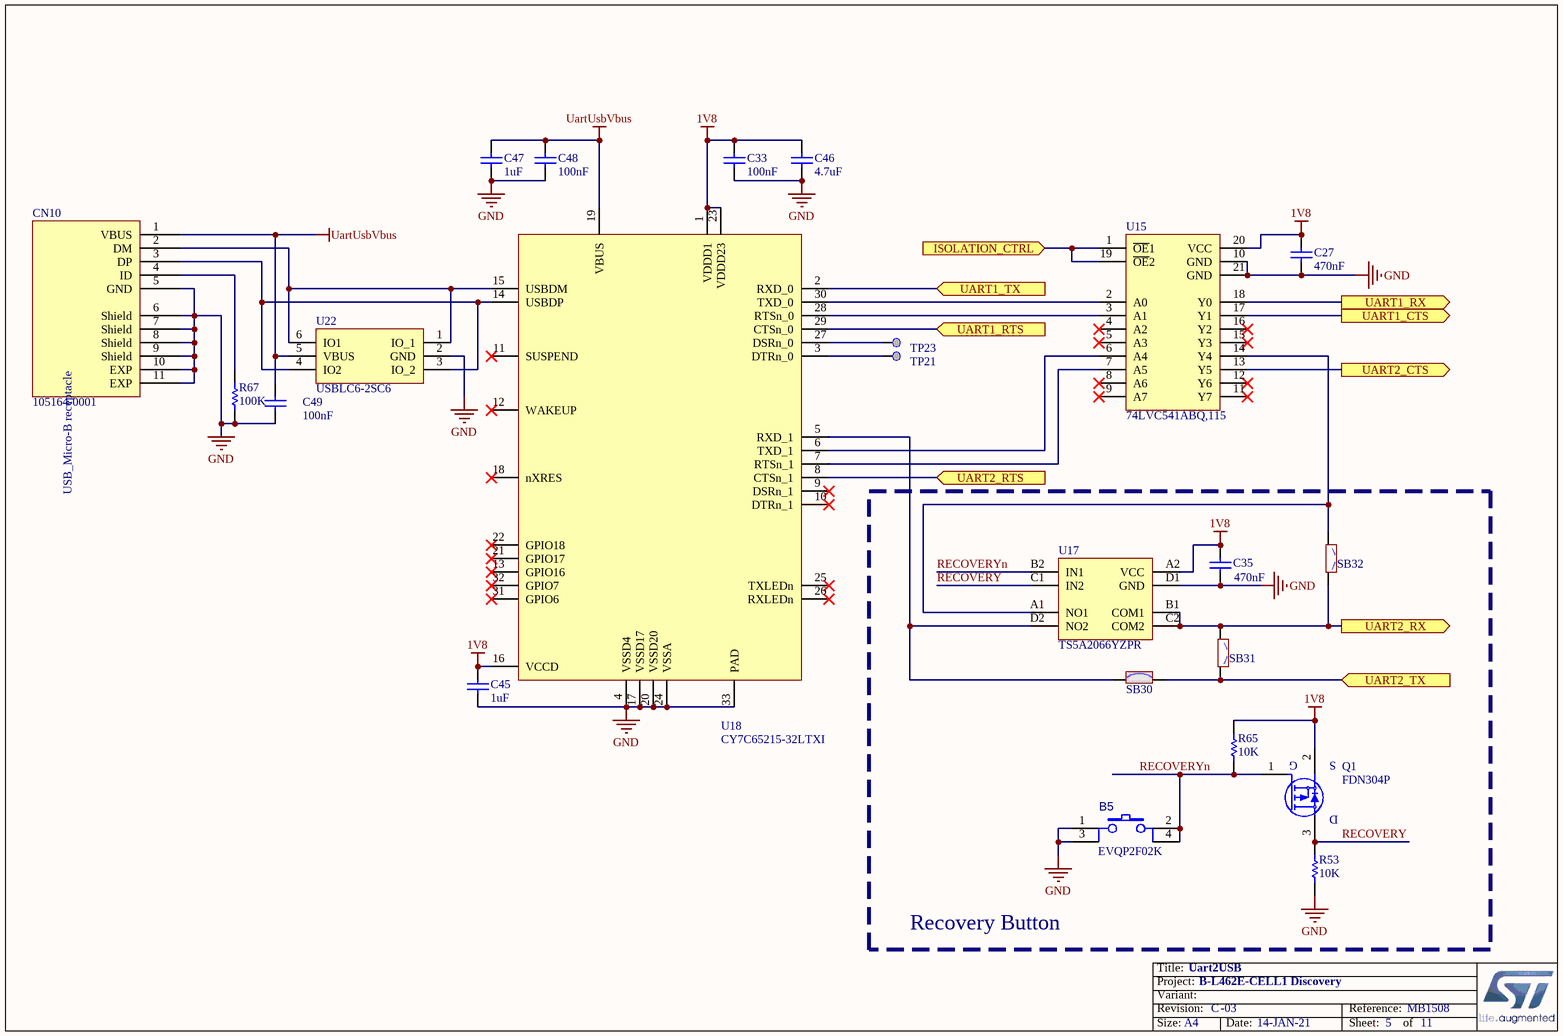
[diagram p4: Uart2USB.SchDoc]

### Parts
B5  value EVQP2F02K  [SWI_PANASONIC_EVQP2F02K]  (hidden comment: SW-PUSH-CMS_EVQP2_BLACK)
C27  value 470nF  [C0603]  (hidden comment: Capacitor)
C33  value 100nF  [C0603]  (hidden comment: Capacitor)
C35  value 470nF  [C0603]  (hidden comment: Capacitor)
C45  value 1uF  [C0603]  (hidden comment: Capacitor)
C46  value 4.7uF  [C0603]  (hidden comment: Capacitor)
C47  value 1uF  [C0603]  (hidden comment: Capacitor)
C48  value 100nF  [C0603]  (hidden comment: Capacitor)
C49  value 100nF  [C0603]  (hidden comment: Capacitor)
CN10  value 105164-0001  [CON_USBMICROB_MOLEX_105164-0001_H2P45]  (hidden comment: USB_uB_105164-0001)
Q1  value FDN304P  [MOS_SOT23]  (hidden comment: MOSFET_FDN304P)
R53  value 10K  [R0603]  (hidden comment: Resistor)
R65  value 10K  [R0603]  (hidden comment: Resistor)
R67  value 100K  [R0603]  (hidden comment: Resistor)
SB30  SB_ON  [SOLDER-BRIDGE_R0603-0R]  (value not drawn)
SB31  SB_OFF  [SOLDER-BRIDGE_R0603-0R]  (value not drawn)
SB32  SB_OFF  [SOLDER-BRIDGE_R0603-0R]  (value not drawn)
TP21  Test Point  [TP_SMD_1MM]  (value not drawn)  (no BOM)
TP23  Test Point  [TP_SMD_1MM]  (value not drawn)  (no BOM)
U15  value 74LVC541ABQ,115  [ICC_DHVQFN20-EPAD_SOT764-1_2P5X4P5_H0P85_P050]  (hidden comment: 74LVC541ABQ)
U17  TS5A2066YZPR  [ICC_DSBGA8_YZP_0P88X1P88_H0P50_P050]
U18  CY7C65215-32LTXI  [ICC_QFN32-EPAD_5X5_P050]
U22  USBLC6-2SC6  [ESD_SOT23-6L]

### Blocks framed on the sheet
Recovery Button: B5 C35 Q1 R53 R65 SB30-SB32 U17

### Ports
ISOLATION_CTRL (in), UART1_CTS (out), UART1_RTS (in), UART1_RX (out), UART1_TX (in), UART2_CTS (out), UART2_RTS (in), UART2_RX (out), UART2_TX (in)

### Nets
1V8: C27.1 C33.2 C35.1 C45.1 C46.1 Q1.2(S) R65.1 U15.20(VCC) U17.A2(VCC) U18.1(VDDD1) U18.16(VCCD) U18.23(VDDD23)
GND: B5.1 B5.3 C27.2 C33.1 C35.2 C45.2 C46.2 C47.2 C48.1 C49.1 CN10.5(GND) CN10.6(Shield) CN10.7(Shield) CN10.8(Shield) CN10.9(Shield) CN10.10(EXP) CN10.11(EXP) R53.2 R67.1 U15.10(GND) U15.21(GND) U17.D1(GND) U18.4(VSSD4) U18.17(VSSD17) U18.20(VSSD20) U18.24(VSSA) U18.33(PAD) U22.2(GND)
UartUsbVbus: C47.1 C48.2 C49.2 CN10.1(VBUS) U18.19(VBUS) U22.5(VBUS)
ISOLATION_CTRL: U15.1(~{OE}1) U15.19(~{OE}2) ; port ISOLATION_CTRL
RECOVERY: Q1.3(D) R53.1 U17.C1(IN2)
RECOVERYn: B5.2 B5.4 Q1.1(G) R65.2 U17.B2(IN1)
RFT_UART1_CTS: U15.17(Y1) ; port UART1_CTS
RFT_UART1_RTS: U18.29(CTSn_0) ; port UART1_RTS
RFT_UART1_RX: U15.18(Y0) ; port UART1_RX
RFT_UART1_TX: U18.2(RXD_0) ; port UART1_TX
RFT_UART2_CTS: U15.13(Y5) ; port UART2_CTS
RFT_UART2_RTS: U18.8(CTSn_1) ; port UART2_RTS
RFT_UART2_RX: SB31.1 SB32.2 U17.B1(COM1) U17.C2(COM2) ; port UART2_RX
RFT_UART2_TX: SB30.2 SB31.2 ; port UART2_TX
NetCN10_2: CN10.2(DM) U18.15(USBDM) U22.1(IO_1) U22.6(IO1)
NetCN10_3: CN10.3(DP) U18.14(USBDP) U22.3(IO_2) U22.4(IO2)
NetCN10_4: CN10.4(ID) R67.2
NetSB30_1: SB30.1 U17.D2(NO2) U18.5(RXD_1)
NetSB32_1: SB32.1 U15.14(Y4) U17.A1(NO1)
NetTP21_1: TP21.1 U18.3(DTRn_0)
NetTP23_1: TP23.1 U18.27(DSRn_0)
NetU15_2: U15.2(A0) U18.30(TXD_0)
NetU15_3: U15.3(A1) U18.28(RTSn_0)
NetU15_6: U15.6(A4) U18.6(TXD_1)
NetU15_7: U15.7(A5) U18.7(RTSn_1)

Not connected (* = marked no-connect by the designer): U15 4(A2)* 5(A3)* 8(A6)* 9(A7)* 11(Y7)* 12(Y6)* 15(Y3)* 16(Y2)*; U18 9(DSRn_1)* 10(DTRn_1)* 11(SUSPEND)* 12(WAKEUP)* 13(GPIO16)* 18(nXRES)* 21(GPIO17)* 22(GPIO18)* 25(TXLEDn)* 26(RXLEDn)* 31(GPIO6)* 32(GPIO7)*

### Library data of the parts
B5 = MCD-00168: as B3 on sheet 1SE_Modem
C27 C35 = MCD-01006: Capacitor, MLCC, 470nF, 16V, X7R, 10%, 0603, T=0.8mm; BMS_Part_Number: 9142003; Part_Preference: Recommended; Manufacturer: YAGEO; Manufacturer_Part_Number: CC0603KRX7R7BB474
C33 C48 C49 = MCD-00237: as C42 on sheet Power
C45 C47 = MCD-00238: as C57 on sheet VoLTE
C46 = MCD-00009: Capacitor, MLCC, 4.7uF, 16V, X5R, +/-10%, 0603, T=0.8mm; Part_Preference: Recommended; Manufacturer: YAGEO; Manufacturer_Part_Number: CC0603KRX5R7BB475
CN10 = MCD-01698: as CN11 on sheet Power
Q1 = MCD-01494: as Q2 on sheet Power
R53 R65 = MCD-00220: as R10 on sheet 1SE_Modem
R67 = MCD-00223: as R59 on sheet Power
SB30 = MCD-00071: as SB34 on sheet Power
SB31 SB32 = MCD-00072: as SB33 on sheet Power
TP21 TP23 = MCD-00074: as TP1 on sheet Power
U15 = MCD-01620: Octal buffer/line driver with 5 V tolerant inputs/outputs; 3-state; Part_Type: IC; Part_Preference: Recommended; Manufacturer: NEXPERIA
U17 = MCD-01624: Dual-Channel 10-Ω SPST Analog Switch; Part_Type: IC; Part_Preference: Recommended; Manufacturer: TEXAS INSTRUMENTS
U18 = MCD-01622: USB-Serial Dual Channel (UART/I2C/SPI) Bridge; Part_Type: IC; Part_Preference: Recommended; Manufacturer: CYPRESS
U22 = MCD-00163: Very low capacitance ESD protection; BMS_Part_Number: 9151075; Part_Type: IC; Part_Preference: Recommended; Manufacturer: STMICROELECTRONICS; Manufacturer_HQ_COO: EU

## Sheet SIM.SchDoc: SIM
size A4; Date: Not used; ApprovedBy: Not used; CheckedBy: Not used; Author: Not used; CompanyName: STMicroelectronics; DrawnBy: Not used; Engineer: Not used; Organization: Not used; Address1: Not used; Address2: Not used; Address3: Not used; Address4: Not used; DocumentNumber: Not used; Revision: Not used; SheetNumber: 3; SheetTotal: 11
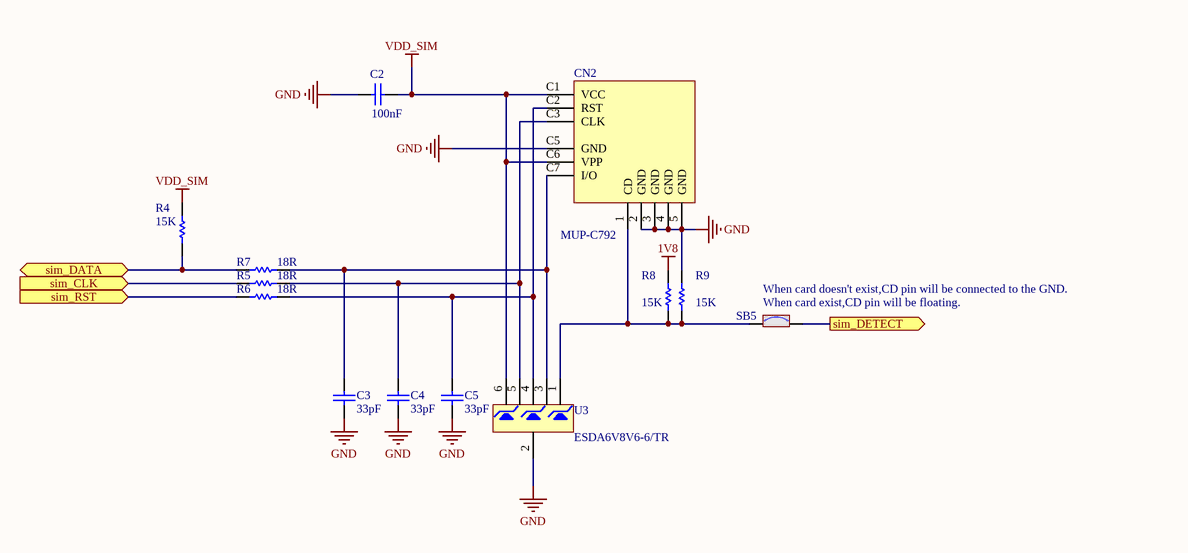
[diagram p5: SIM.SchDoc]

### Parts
C2  value 100nF  [C0402]  (hidden comment: Capacitor)
C3  value 33pF  [C0402]  (hidden comment: Capacitor)
C4  value 33pF  [C0402]  (hidden comment: Capacitor)
C5  value 33pF  [C0402]  (hidden comment: Capacitor)
CN2  MUP-C792  [CON_MICRO-SIMCARD_MUP_MUP-C792]
R4  value 15K  [R0402]  (hidden comment: Resistor)
R5  value 18R  [R0402]  (hidden comment: Resistor)
R6  value 18R  [R0402]  (hidden comment: Resistor)
R7  value 18R  [R0402]  (hidden comment: Resistor)
R8  value 15K  [R0402]  (hidden comment: Resistor)
R9  value 15K  [R0402]  (hidden comment: Resistor)
SB5  SB_ON  [SOLDER-BRIDGE_R0603-0R]  (value not drawn)
U3  ESDA6V8V6-6/TR  [ESD_SOT563-6L_P050]

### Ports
sim_CLK (in), sim_DATA (bidir), sim_DETECT (out), sim_RST (in)

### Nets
1V8: R8.2
GND: C2.2 C3.1 C4.1 C5.1 CN2.2(GND) CN2.3(GND) CN2.4(GND) CN2.5(GND) CN2.C5(GND) R9.2 U3.2
VDD_SIM: C2.1 CN2.C1(VCC) CN2.C6(VPP) R4.2 U3.6
NC_SIM_CLK: R5.1 ; port sim_CLK
NC_SIM_DETECT: SB5.2 ; port sim_DETECT
NC_SIM_IO: R4.1 R7.1 ; port sim_DATA
NC_SIM_RST: R6.1 ; port sim_RST
NetC3_2: C3.2 CN2.C7(I/O) R7.2 U3.3
NetC4_2: C4.2 CN2.C3(CLK) R5.2 U3.5
NetC5_2: C5.2 CN2.C2(RST) R6.2 U3.4
NetCN2_1: CN2.1(CD) R8.1 R9.1 SB5.1 U3.1

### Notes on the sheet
- (near SB5) When card doesn't exist,CD pin will be connected to the GND.
- (near SB5) When card exist,CD pin will be floating.

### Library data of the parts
C2 = MCD-00006: Capacitor, MLCC, 100nF, 16V, X7R, +/-10%, 0402, T=0.5mm; Part_Preference: Recommended; Manufacturer: YAGEO; Manufacturer_Part_Number: CC0402KRX7R7BB104; Alternate_Manufacturer: MURATA; Alternate_Manufacturer_Part_Number: GCM155R71C104KA55D; Order_Code_RS: 616-9701
C3-C5 = MCD-00277: Capacitor, MLCC, 33pF, 50V, NPO,+/- 5%, 0402, T=0,5mm; Part_Preference: Recommended; Manufacturer: YAGEO; Manufacturer_Part_Number: CC0402JRNPO9BN330
CN2 = MCD-01699: Socket_microsim 17.17*16.75, height 1.5mm, 6PIN; Part_Type: Connector; Part_Preference: Recommended; Manufacturer: MUP
R4 R8 R9 = MCD-00285: Resistor,15K,0402,5%,1/16W; Part_Preference: Recommended; Manufacturer: YAGEO; Manufacturer_Part_Number: RC0402JR-0715KL
R5-R7 = MCD-00286: Resistor,18R,0402,5%,1/16W; Part_Preference: Recommended; Manufacturer: YAGEO; Manufacturer_Part_Number: RC0402JR-0718RL
SB5 = MCD-00071: as SB34 on sheet Power
U3 = MCD-01696: ESD protection; Part_Type: Diode; Part_Preference: Recommended; Manufacturer: WILLSEMI

## Sheet 1SE_MCU.SchDoc: 1SE_MCU
size A4; Date: Not used; ApprovedBy: Not used; CheckedBy: Not used; Author: Not used; CompanyName: STMicroelectronics; DrawnBy: Not used; Engineer: Not used; Organization: Not used; Address1: Not used; Address2: Not used; Address3: Not used; Address4: Not used; DocumentNumber: Not used; Revision: Not used; SheetNumber: 6; SheetTotal: 11
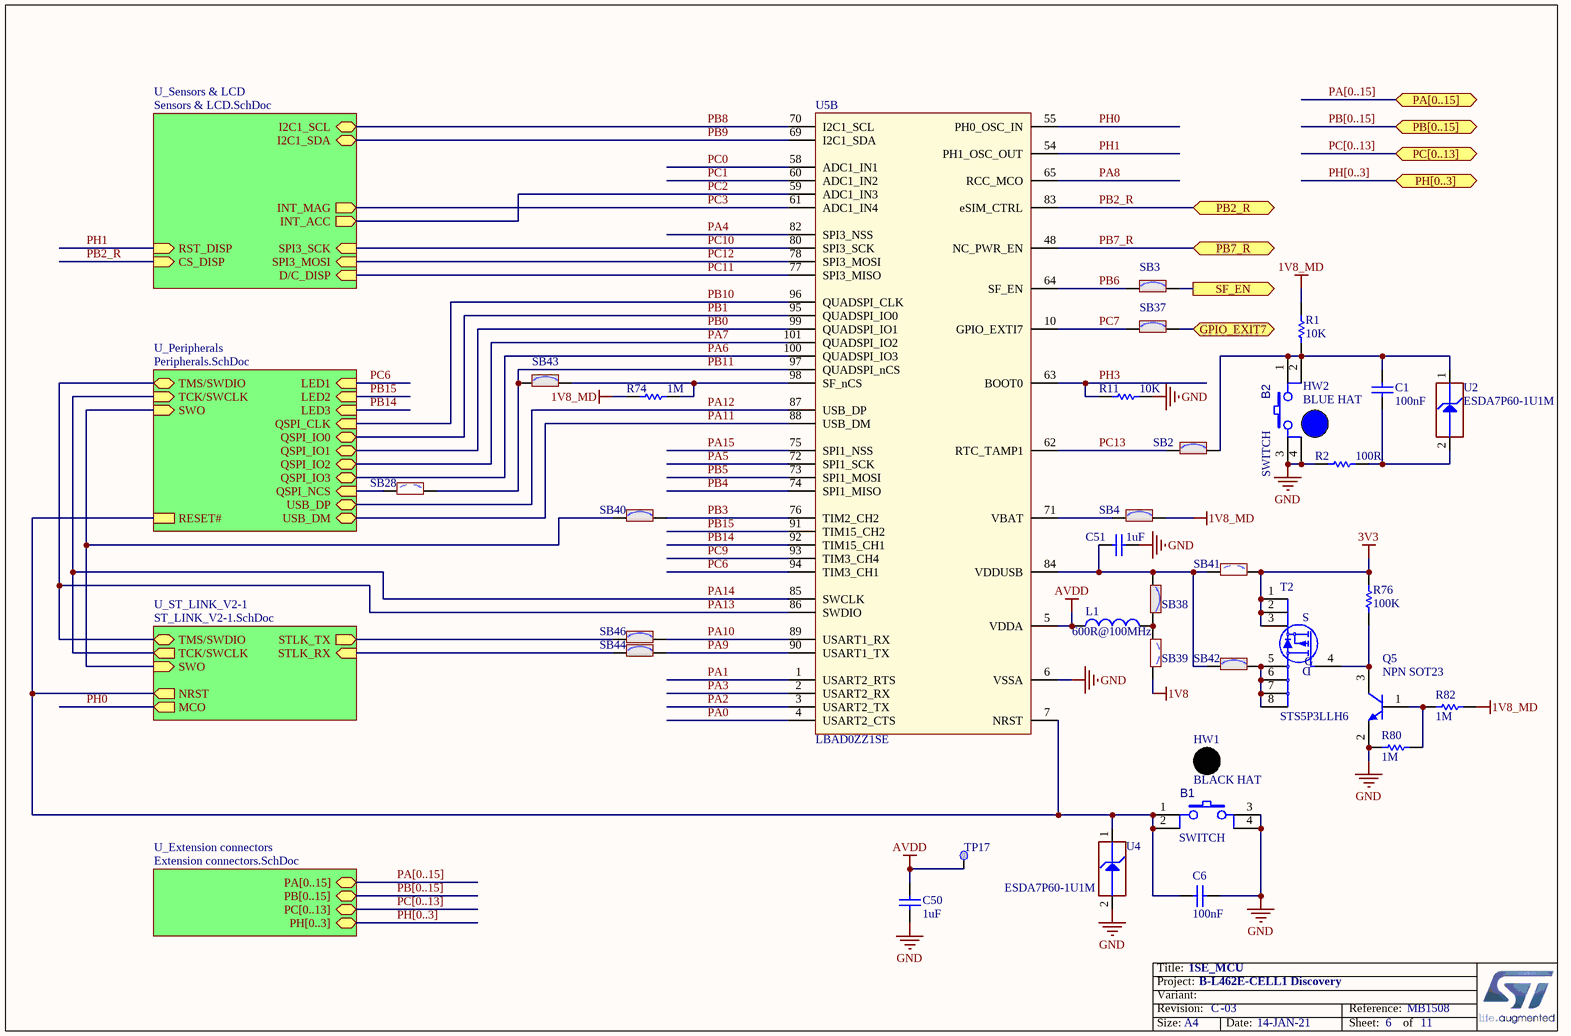
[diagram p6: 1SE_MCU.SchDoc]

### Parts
B1  value SWITCH  [SWI_WEALTHMETAL_TD-0341_4P_BLACK]  (hidden comment: SW-PUSH-CMS)
B2  value SWITCH  [SWI_WEALTHMETAL_TD-0341_4P_BLUE]  (hidden comment: SW-PUSH-CMS)
C1  value 100nF  [C0402]  (hidden comment: Capacitor)
C6  value 100nF  [C0402]  (hidden comment: Capacitor)
C50  value 1uF  [C0603]  (hidden comment: Capacitor)
C51  value 1uF  [C0603]  (hidden comment: Capacitor)
HW1  value BLACK HAT  (hidden comment: BUTTON_HAT_BLACK)  (mechanical)
HW2  value BLUE HAT  (hidden comment: BUTTON_HAT_BLUE)  (mechanical)
L1  value 600R@100MHz  [L0603]  (hidden comment: BEAD)
Q5  value NPN SOT23  [NPN_SOT23]  (hidden comment: 9013-SOT23)
R1  value 10K  [R0603]  (hidden comment: Resistor)
R2  value 100R  [R0603]  (hidden comment: Resistor)
R11  value 10K  [R0603]  (hidden comment: Resistor)
R74  value 1M  [R0603]  (hidden comment: Resistor)
R76  value 100K  [R0603]  (hidden comment: Resistor)
R80  value 1M  [R0603]  (hidden comment: Resistor)
R82  value 1M  [R0603]  (hidden comment: Resistor)
SB2  SB_ON  [SOLDER-BRIDGE_R0603-0R]  (value not drawn)
SB3  SB_ON  [SOLDER-BRIDGE_R0603-0R]  (value not drawn)
SB4  SB_ON  [SOLDER-BRIDGE_R0603-0R]  (value not drawn)
SB28  SB_OFF  [SOLDER-BRIDGE_R0603-0R]  (value not drawn)
SB37  SB_ON  [SOLDER-BRIDGE_R0603-0R]  (value not drawn)
SB38  SB_ON  [SOLDER-BRIDGE_R0603-0R]  (value not drawn)
SB39  SB_OFF  [SOLDER-BRIDGE_R0603-0R]  (value not drawn)
SB40  SB_ON  [SOLDER-BRIDGE_R0603-0R]  (value not drawn)
SB41  SB_OFF  [SOLDER-BRIDGE_R0603-0R]  (value not drawn)
SB42  SB_ON  [SOLDER-BRIDGE_R0603-0R]  (value not drawn)
SB43  SB_ON  [SOLDER-BRIDGE_R0603-0R]  (value not drawn)
SB44  SB_ON  [SOLDER-BRIDGE_R0603-0R]  (value not drawn)
SB46  SB_ON  [SOLDER-BRIDGE_R0603-0R]  (value not drawn)
T2  STS5P3LLH6  [ICC_SO8_5X4_P127]
TP17  Test Point  [TP_SMD_1MM]  (value not drawn)  (no BOM)
U2  value ESDA7P60-1U1M  [ESD_QFN2_1P6X1_P125]  (hidden comment: ESD-TRANSIL)
U4  value ESDA7P60-1U1M  [ESD_QFN2_1P6X1_P125]  (hidden comment: ESD-TRANSIL)
U5  value LBAD0ZZ1SE  [MOD_BOARD_MURATA_TYPE-1SE_ES3]  (hidden comment: NBIoT_Mod_Type1SE)  (part B of 3)

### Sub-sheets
U_Extension connectors = Extension connectors.SchDoc: PA[0..15] (bidir), PB[0..15] (bidir), PC[0..13] (bidir), PH[0..3] (bidir)
U_Peripherals = Peripherals.SchDoc: LED1 (in), LED2 (in), LED3 (in), SWO (in), RESET#, USB_DM (bidir), USB_DP (bidir), TCK/SWCLK (in), TMS/SWDIO (bidir), QSPI_NCS (in), QSPI_CLK (in), QSPI_IO0 (bidir), QSPI_IO1 (bidir), QSPI_IO2 (bidir), QSPI_IO3 (bidir)
U_Sensors & LCD = Sensors & LCD.SchDoc: I2C1_SCL (bidir), I2C1_SDA (bidir), INT_MAG (out), INT_ACC (out), CS_DISP (in), RST_DISP (in), D/C_DISP (in), SPI3_SCK (in), SPI3_MOSI (in)
U_ST_LINK_V2-1 = ST_LINK_V2-1.SchDoc: TMS/SWDIO (bidir), TCK/SWCLK (out), MCO (out), NRST (out), STLK_RX (in), STLK_TX (out), SWO (in)

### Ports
GPIO_EXIT7 (bidir), PA[0..15] (bidir), PB2_R (bidir), PB7_R (bidir), PB[0..15] (bidir), PC[0..13] (bidir), PH[0..3] (bidir), SF_EN (out)

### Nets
1V8: SB39.2
1V8_MD: R1.2 R74.2 R82.2 SB4.2
3V3: R76.2 SB41.2 T2.1(S) T2.2(S) T2.3(S)
AVDD: C50.1 L1.1 TP17.1 U5.5(VDDA)
GND: B1.3 B1.4 B2.3 B2.4 C6.1 C50.2 C51.2 Q5.2(E) R2.1 R11.1 R80.1 U4.2(GND) U5.6(VSSA)
NC_RST_IND: SB37.2 ; port GPIO_EXIT7
NRST: B1.1 B1.2 C6.2 U4.1(IO1) U5.7(NRST) ; sheet U_Peripherals/RESET#, sheet U_ST_LINK_V2-1/NRST
PA0: U5.4(USART2_CTS)
PA1: U5.1(USART2_RTS)
PA2: U5.3(USART2_TX)
PA3: U5.2(USART2_RX)
PA4: U5.82(SPI3_NSS)
PA5: U5.72(SPI1_SCK)
PA6: U5.100(QUADSPI_IO3) ; sheet U_Peripherals/QSPI_IO3
PA7: U5.101(QUADSPI_IO2) ; sheet U_Peripherals/QSPI_IO2
PA8: U5.65(RCC_MCO)
PA9: SB44.2 U5.90(USART1_TX)
PA10: SB46.2 U5.89(USART1_RX)
PA11: U5.88(USB_DM) ; sheet U_Peripherals/USB_DM
PA12: U5.87(USB_DP) ; sheet U_Peripherals/USB_DP
PA13: U5.86(SWDIO) ; sheet U_Peripherals/TMS/SWDIO, sheet U_ST_LINK_V2-1/TMS/SWDIO
PA14: U5.85(SWCLK) ; sheet U_Peripherals/TCK/SWCLK, sheet U_ST_LINK_V2-1/TCK/SWCLK
PA15: U5.75(SPI1_NSS)
PB0: U5.99(QUADSPI_IO1) ; sheet U_Peripherals/QSPI_IO1
PB1: U5.95(QUADSPI_IO0) ; sheet U_Peripherals/QSPI_IO0
PB2_R: U5.83(eSIM_CTRL) ; port PB2_R, sheet U_Sensors & LCD/CS_DISP
PB3: SB40.2 U5.76(TIM2_CH2)
PB4: U5.74(SPI1_MISO)
PB5: U5.73(SPI1_MOSI)
PB6: SB3.1 U5.64(SF_EN)
PB7_R: U5.48(NC_PWR_EN) ; port PB7_R
PB8: U5.70(I2C1_SCL) ; sheet U_Sensors & LCD/I2C1_SCL  [project net I2C1_SCL]
PB9: U5.69(I2C1_SDA) ; sheet U_Sensors & LCD/I2C1_SDA  [project net I2C1_SDA]
PB10: U5.96(QUADSPI_CLK) ; sheet U_Peripherals/QSPI_CLK
PB11: SB28.2 SB43.1 U5.97(QUADSPI_nCS)
PB14: U5.92(TIM15_CH1) ; sheet U_Peripherals/LED3
PB15: U5.91(TIM15_CH2) ; sheet U_Peripherals/LED2
PC0: U5.58(ADC1_IN1)
PC1: U5.60(ADC1_IN2)
PC2: U5.59(ADC1_IN3) ; sheet U_Sensors & LCD/INT_ACC
PC3: U5.61(ADC1_IN4) ; sheet U_Sensors & LCD/INT_MAG
PC6: U5.94(TIM3_CH1) ; sheet U_Peripherals/LED1
PC7: SB37.1 U5.10(GPIO_EXTI7)
PC9: U5.93(TIM3_CH4)
PC10: U5.80(SPI3_SCK) ; sheet U_Sensors & LCD/SPI3_SCK
PC11: U5.77(SPI3_MISO) ; sheet U_Sensors & LCD/D/C_DISP
PC12: U5.78(SPI3_MOSI) ; sheet U_Sensors & LCD/SPI3_MOSI
PC13: SB2.1 U5.62(RTC_TAMP1)
PH0: U5.55(PH0_OSC_IN) ; sheet U_ST_LINK_V2-1/MCO  [project net MCO]
PH1: U5.54(PH1_OSC_OUT) ; sheet U_Sensors & LCD/RST_DISP
PH3: R11.2 U5.63(BOOT0)
QSPI_NCS: SB28.1 ; sheet U_Peripherals/QSPI_NCS
SF_EN: SB3.2 ; port SF_EN
STLK_RX: SB44.1 ; sheet U_ST_LINK_V2-1/STLK_RX
STLK_TX: SB46.1 ; sheet U_ST_LINK_V2-1/STLK_TX
SWO: SB40.1 ; sheet U_Peripherals/SWO, sheet U_ST_LINK_V2-1/SWO
NetB2_1: B2.1 B2.2 C1.2 R1.1 SB2.2 U2.1(IO1)
NetC1_1: C1.1 R2.2 U2.2(GND)
NetC51_1: C51.1 SB38.1 SB41.1 SB42.1 U5.84(VDDUSB)
NetL1_2: L1.2 SB38.2 SB39.1
NetQ5_1: Q5.1(B) R80.2 R82.1
NetQ5_3: Q5.3(C) R76.1 T2.4(G)
NetR74_1: R74.1 SB43.2 U5.98(SF_nCS)
NetSB4_1: SB4.1 U5.71(VBAT)
NetSB42_2: SB42.2 T2.5(D) T2.6(D) T2.7(D) T2.8(D)

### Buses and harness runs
bus PA[0..15] = port PA[0..15]
bus PA[0..15] = sheet U_Extension connectors/PA[0..15]
bus PB[0..15] = port PB[0..15]
bus PB[0..15] = sheet U_Extension connectors/PB[0..15]
bus PC[0..13] = port PC[0..13]
bus PC[0..13] = sheet U_Extension connectors/PC[0..13]
bus PH[0..3] = port PH[0..3]
bus PH[0..3] = sheet U_Extension connectors/PH[0..3]

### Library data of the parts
B1 = MCD-00001: Non-Open Push-Button 0.1A 24V BLACK; Part_Type: Misc; Part_Preference: Recommended; Manufacturer: WEALTHMETAL; Manufacturer_Part_Number: TD-0341
B2 = MCD-00002: Non-Open Push-Button 0.1A 24V; Part_Type: Misc; Part_Preference: Recommended; Manufacturer: WEALTHMETAL; Manufacturer_Part_Number: TD-0341
C1 C6 = MCD-00102: Capacitor, MLCC, 100nF, 16V, X7R, +/-10%, 0402, T=0,5mm; Part_Preference: Not recommended; Manufacturer: YAGEO; Manufacturer_Part_Number: CC0402KRX7R7BB104; Alternate_Manufacturer: MURATA; Alternate_Manufacturer_Part_Number: GCM155R71C104KA55D; Order_Code_RS: 616-9701
C50 C51 = MCD-00238: as C57 on sheet VoLTE
HW1 = MCD-00635: Black Hat for switch TD0341X-G01-BLA; Part_Type: Misc; Part_Preference: Not recommended; Manufacturer: JIUBABA; Manufacturer_Part_Number: 988.16.09.3.00003_SH-517
HW2 = MCD-00634: Blue Hat for switch TD0341X-G01-BLU; Part_Type: Misc; Part_Preference: Not recommended; Manufacturer: JIUBABA; Manufacturer_Part_Number: 988.16.09.3.00002_SH-517
L1 = MCD-00047: SMD Chip ferrite bead, 600R@100MHz +/-25%, 350mA, 500mohm DC, 0603, T=0.8mm; Part_Type: Inductor; Part_Preference: Recommended; Manufacturer: TAI-TECH; Manufacturer_Part_Number: FCM1608KF-601T03
Q5 = MCD-00073: as Q4 on sheet 1SE_Modem
R1 R11 = MCD-00220: as R10 on sheet 1SE_Modem
R2 = MCD-00224: Resistor,100R,0603,1%,1/10W; Part_Preference: Recommended; Manufacturer: YAGEO; Manufacturer_Part_Number: RC0603FR-07100RL
R74 R80 R82 = MCD-00257: as R58 on sheet Power
R76 = MCD-00223: as R59 on sheet Power
SB2-SB4 SB37 SB38 SB40 SB42-SB44 SB46 = MCD-00071: as SB34 on sheet Power
SB28 SB39 SB41 = MCD-00072: as SB33 on sheet Power
T2 = MCD-01964: Tansistor, P-Channel 30 V, 0.048 Ohm typ., 5 A STripFET H6 Power MOSFET in SO-8 package; Part_Type: Transistor; Part_Preference: Recommended; Manufacturer: STMICROELECTRONICS; Manufacturer_HQ_COO: EU; Component_Country_Of_Origin: China
TP17 = MCD-00074: as TP1 on sheet Power
U2 U4 = MCD-00251: as U21 on sheet Power
U5 = MCD-01700: as U5 on sheet 1SE_Modem

## Sheet Extension connectors.SchDoc: Extension connector
size A4; Date: Not used; ApprovedBy: Not used; CheckedBy: Not used; Author: Not used; CompanyName: STMicroelectronics; DrawnBy: Not used; Engineer: Not used; Organization: Not used; Address1: Not used; Address2: Not used; Address3: Not used; Address4: Not used; DocumentNumber: Not used; Revision: Not used; SheetNumber: 7; SheetTotal: 11
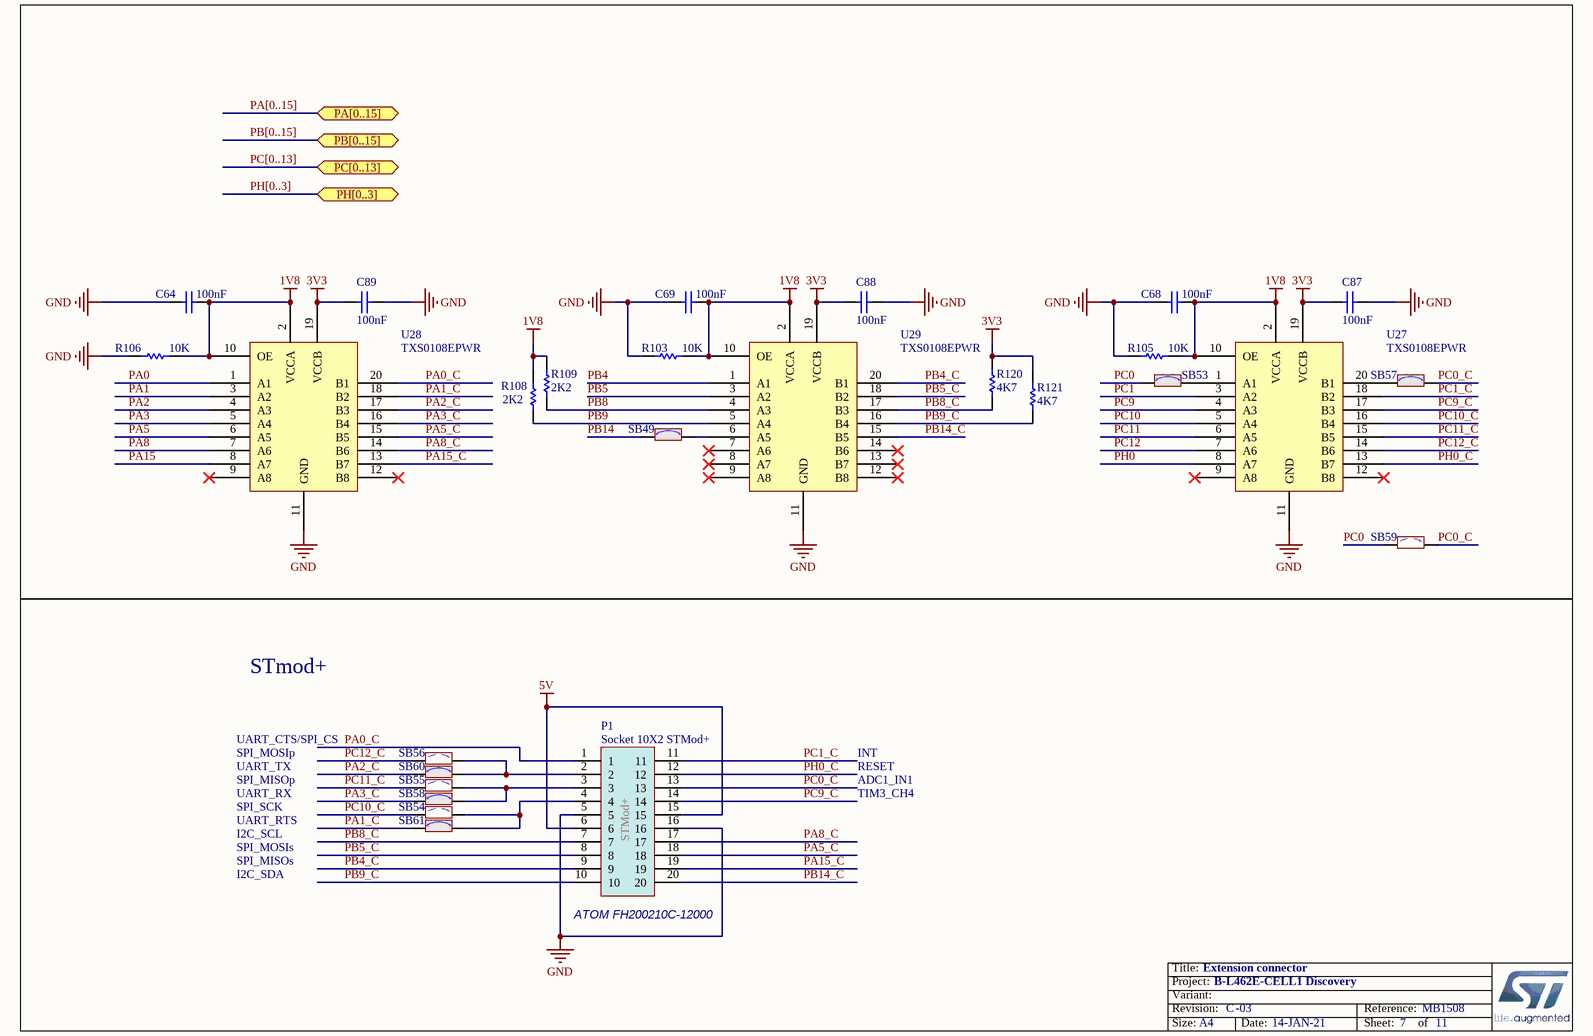
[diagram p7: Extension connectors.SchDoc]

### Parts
C64  value 100nF  [C0603]  (hidden comment: Capacitor)
C68  value 100nF  [C0603]  (hidden comment: Capacitor)
C69  value 100nF  [C0603]  (hidden comment: Capacitor)
C87  value 100nF  [C0603]  (hidden comment: Capacitor)
C88  value 100nF  [C0603]  (hidden comment: Capacitor)
C89  value 100nF  [C0603]  (hidden comment: Capacitor)
P1  Socket 10X2 STMod+  [CON_SAMTEC_SQT-110-01-F-D-RA__STMOD+]
R103  value 10K  [R0603]  (hidden comment: Resistor)
R105  value 10K  [R0603]  (hidden comment: Resistor)
R106  value 10K  [R0603]  (hidden comment: Resistor)
R108  value 2K2  [R0603]  (hidden comment: Resistor)
R109  value 2K2  [R0603]  (hidden comment: Resistor)
R120  value 4K7  [R0603]  (hidden comment: Resistor)
R121  value 4K7  [R0603]  (hidden comment: Resistor)
SB49  SB_ON  [SOLDER-BRIDGE_R0603-0R]  (value not drawn)
SB53  SB_ON  [SOLDER-BRIDGE_R0603-0R]  (value not drawn)
SB54  SB_OFF  [SOLDER-BRIDGE_R0603-0R]  (value not drawn)
SB55  SB_OFF  [SOLDER-BRIDGE_R0603-0R]  (value not drawn)
SB56  SB_OFF  [SOLDER-BRIDGE_R0603-0R]  (value not drawn)
SB57  SB_ON  [SOLDER-BRIDGE_R0603-0R]  (value not drawn)
SB58  SB_ON  [SOLDER-BRIDGE_R0603-0R]  (value not drawn)
SB59  SB_OFF  [SOLDER-BRIDGE_R0603-0R]  (value not drawn)
SB60  SB_ON  [SOLDER-BRIDGE_R0603-0R]  (value not drawn)
SB61  SB_ON  [SOLDER-BRIDGE_R0603-0R]  (value not drawn)
U27  TXS0108EPWR  [ICC_TSSOP20_6P50X4P40_P065]
U28  TXS0108EPWR  [ICC_TSSOP20_6P50X4P40_P065]
U29  TXS0108EPWR  [ICC_TSSOP20_6P50X4P40_P065]

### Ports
PA[0..15] (bidir), PB[0..15] (bidir), PC[0..13] (bidir), PH[0..3] (bidir)

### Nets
1V8: C64.1 C68.1 C69.1 R103.1 R105.1 R106.1 R108.1 R109.1 U27.2(VCCA) U27.10(OE) U28.2(VCCA) U28.10(OE) U29.2(VCCA) U29.10(OE)
3V3: C87.2 C88.2 C89.2 R120.1 R121.1 U27.19(VCCB) U28.19(VCCB) U29.19(VCCB)
5V: P1.6 P1.15
GND: C64.2 C68.2 C69.2 C87.1 C88.1 C89.1 P1.5 P1.16 R103.2 R105.2 R106.2 U27.11(GND) U28.11(GND) U29.11(GND)
PA0: U28.1(A1)
PA0_C: P1.1 U28.20(B1)
PA1: U28.3(A2)
PA1_C: SB61.1 U28.18(B2)
PA2: U28.4(A3)
PA2_C: SB60.1 U28.17(B3)
PA3: U28.5(A4)
PA3_C: SB58.1 U28.16(B4)
PA5: U28.6(A5)
PA5_C: P1.18 U28.15(B5)
PA8: U28.7(A6)
PA8_C: P1.17 U28.14(B6)
PA15: U28.8(A7)
PA15_C: P1.19 U28.13(B7)
PB4: U29.1(A1)
PB4_C: P1.9 U29.20(B1)
PB5: U29.3(A2)
PB5_C: P1.8 U29.18(B2)
PB8: R109.2 U29.4(A3)  [project net I2C1_SCL]
PB8_C: P1.7 R120.2 U29.17(B3)
PB9: R108.2 U29.5(A4)  [project net I2C1_SDA]
PB9_C: P1.10 R121.2 U29.16(B4)
PB14: SB49.1
PB14_C: P1.20 U29.15(B5)
PC0: SB53.1 SB59.1
PC0_C: P1.13 SB57.2 SB59.2
PC1: U27.3(A2)
PC1_C: P1.11 U27.18(B2)
PC9: U27.4(A3)
PC9_C: P1.14 U27.17(B3)
PC10: U27.5(A4)
PC10_C: SB54.1 U27.16(B4)
PC11: U27.6(A5)
PC11_C: SB55.1 U27.15(B5)
PC12: U27.7(A6)
PC12_C: SB56.1 U27.14(B6)
PH0: U27.8(A7)  [project net MCO]
PH0_C: P1.12 U27.13(B7)
NetP1_2: P1.2 SB56.2 SB60.2
NetP1_3: P1.3 SB55.2 SB58.2
NetP1_4: P1.4 SB54.2 SB61.2
NetSB49_2: SB49.2 U29.6(A5)
NetSB53_2: SB53.2 U27.1(A1)
NetSB57_1: SB57.1 U27.20(B1)

Not connected (* = marked no-connect by the designer): U27 9(A8)* 12(B8)*; U28 9(A8)* 12(B8)*; U29 7(A6)* 8(A7)* 9(A8)* 12(B8)* 13(B7)* 14(B6)*

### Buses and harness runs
bus PA[0..15] = port PA[0..15]
bus PB[0..15] = port PB[0..15]
bus PC[0..13] = port PC[0..13]
bus PH[0..3] = port PH[0..3]

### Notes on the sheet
- STmod+
- UART_CTS/SPI_CS
- SPI_MOSIp
- UART_TX
- SPI_MISOp
- INT
- ADC1_IN1
- RESET
- UART_RX
- SPI_SCK
- UART_RTS
- I2C_SCL
- SPI_MOSIs
- TIM3_CH4
- SPI_MISOs
- I2C_SDA
- (near P1) ATOM FH200210C-12000

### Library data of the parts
C64 C68 C69 C87-C89 = MCD-00237: as C42 on sheet Power
P1 = MCD-00309: Socket 10x2, 2.00mm, RA, TH, Height 6.35mm/2.29mm; Part_Type: Connector; Part_Preference: Recommended; Manufacturer: SAMTEC; Manufacturer_Part_Number: SQT-110-01-F-D-RA; Alternate_Manufacturer: JIUBABA;CONNECT; Alternate_Manufacturer_Part_Number: FH200020C-12300;CNT-F200-2*10-GD-635/2.3
R103 R105 R106 = MCD-00220: as R10 on sheet 1SE_Modem
R108 R109 = MCD-00349: Resistor,2K2,0603,1%,1/10W; Part_Preference: Recommended; Manufacturer: YAGEO; Manufacturer_Part_Number: RC0603FR-072K2L
R120 R121 = MCD-00219: Resistor,4K7,0603,1%,1/10W; Part_Preference: Recommended; Manufacturer: YAGEO; Manufacturer_Part_Number: RC0603FR-074K7L
SB49 SB53 SB57 SB58 SB60 SB61 = MCD-00071: as SB34 on sheet Power
SB54-SB56 SB59 = MCD-00072: as SB33 on sheet Power
U27-U29 = MCD-00289: 8bits_bidirectionnal level shifter, Delay 312ns/1V8; Part_Type: IC; Part_Preference: Recommended; Manufacturer: TEXAS INSTRUMENTS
